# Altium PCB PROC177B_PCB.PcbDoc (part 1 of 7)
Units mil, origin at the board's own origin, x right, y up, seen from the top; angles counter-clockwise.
Board outline 4257.98 x 1561.15 mil, 4 copper layers (Top Layer, Int1 (GND), Int2 (PWR), Bottom Layer), stack 63.572 mil thick; 461 components, 307 nets, 1564 pads, 607 vias.
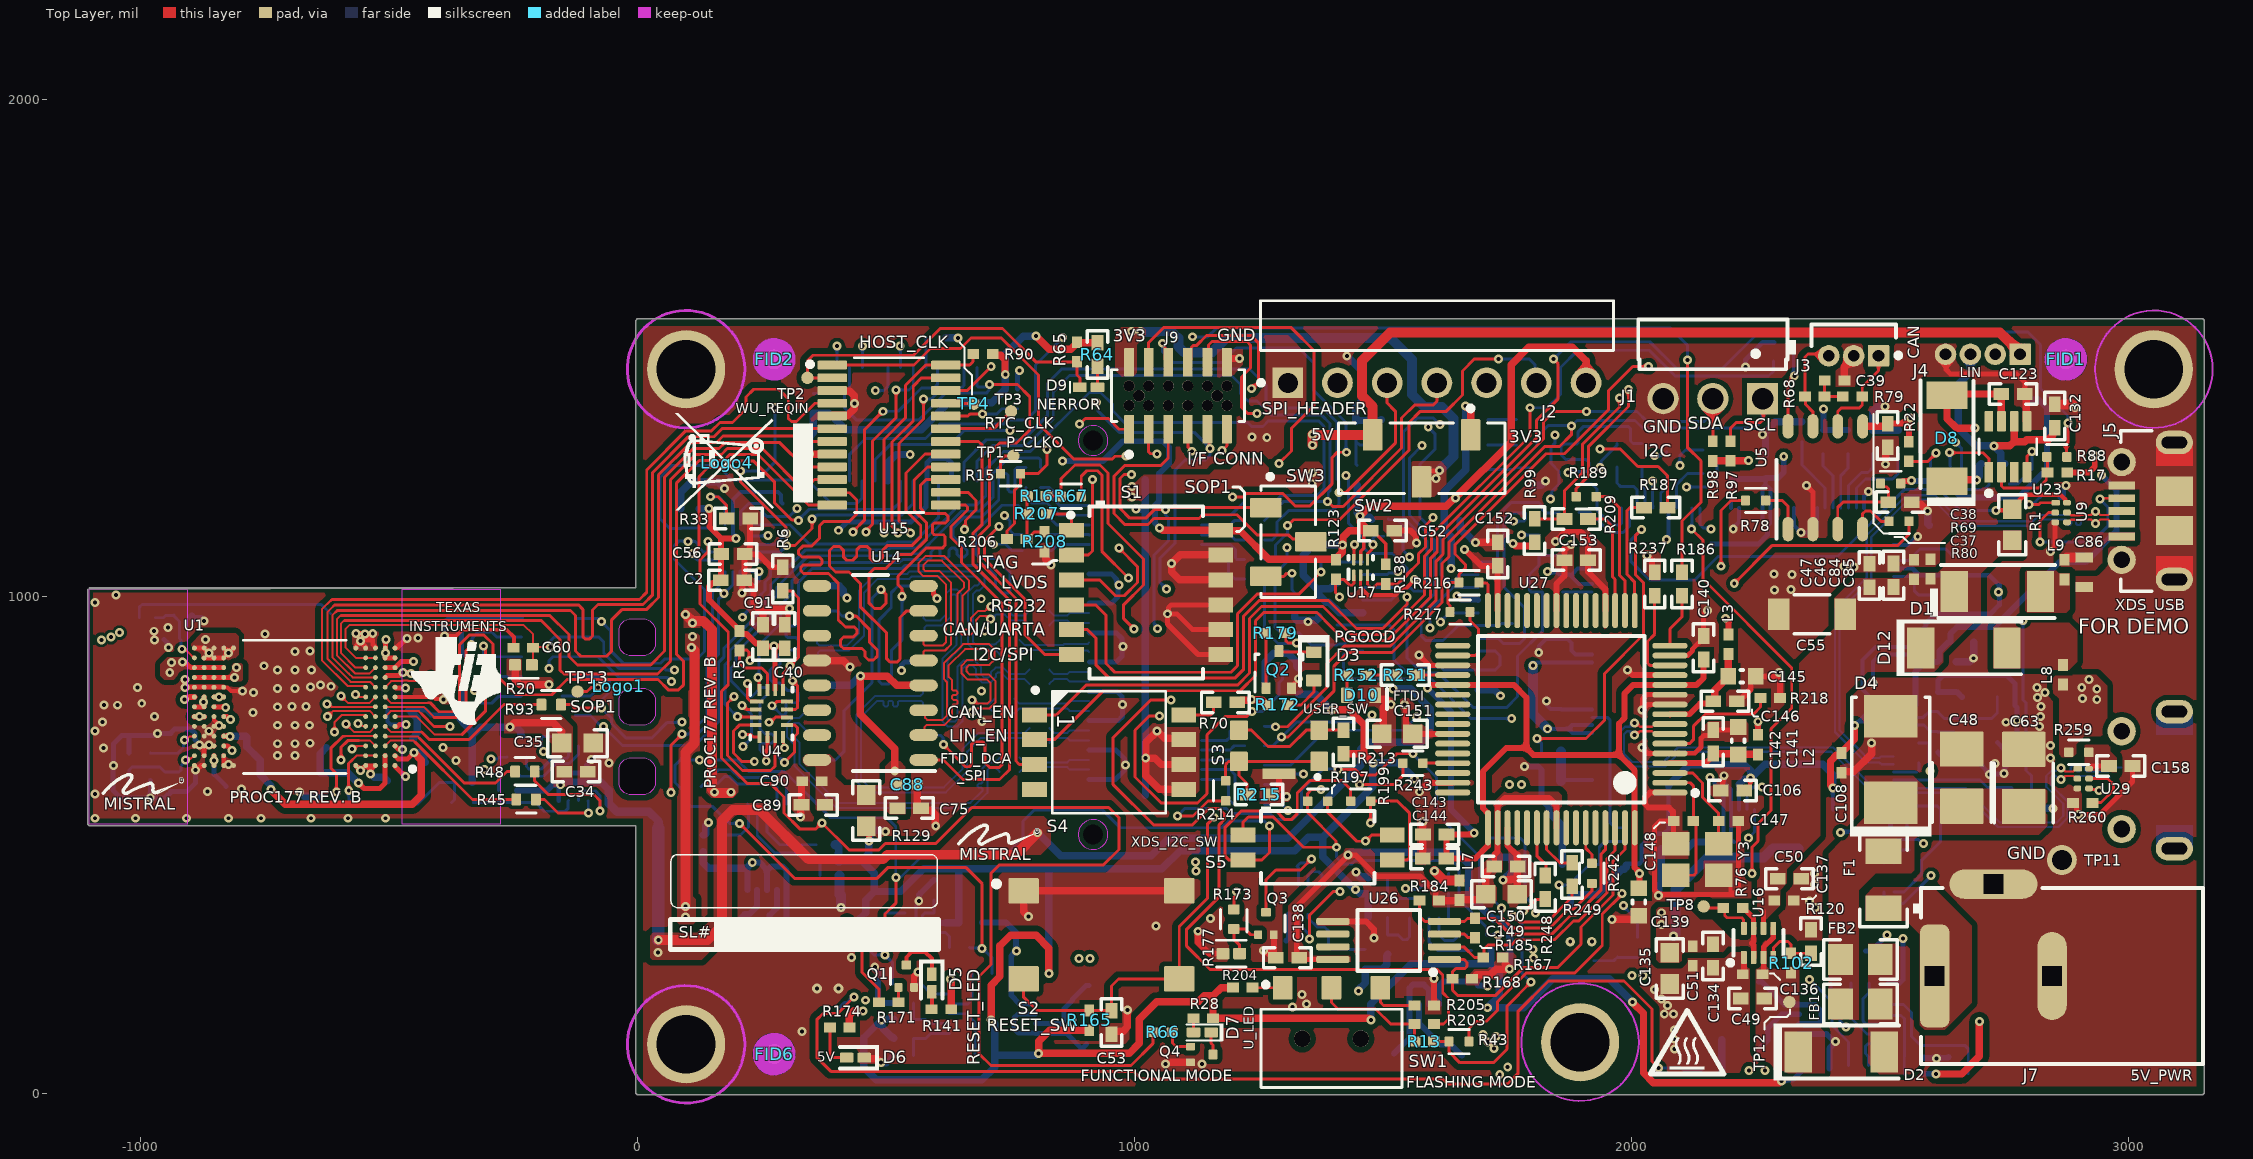
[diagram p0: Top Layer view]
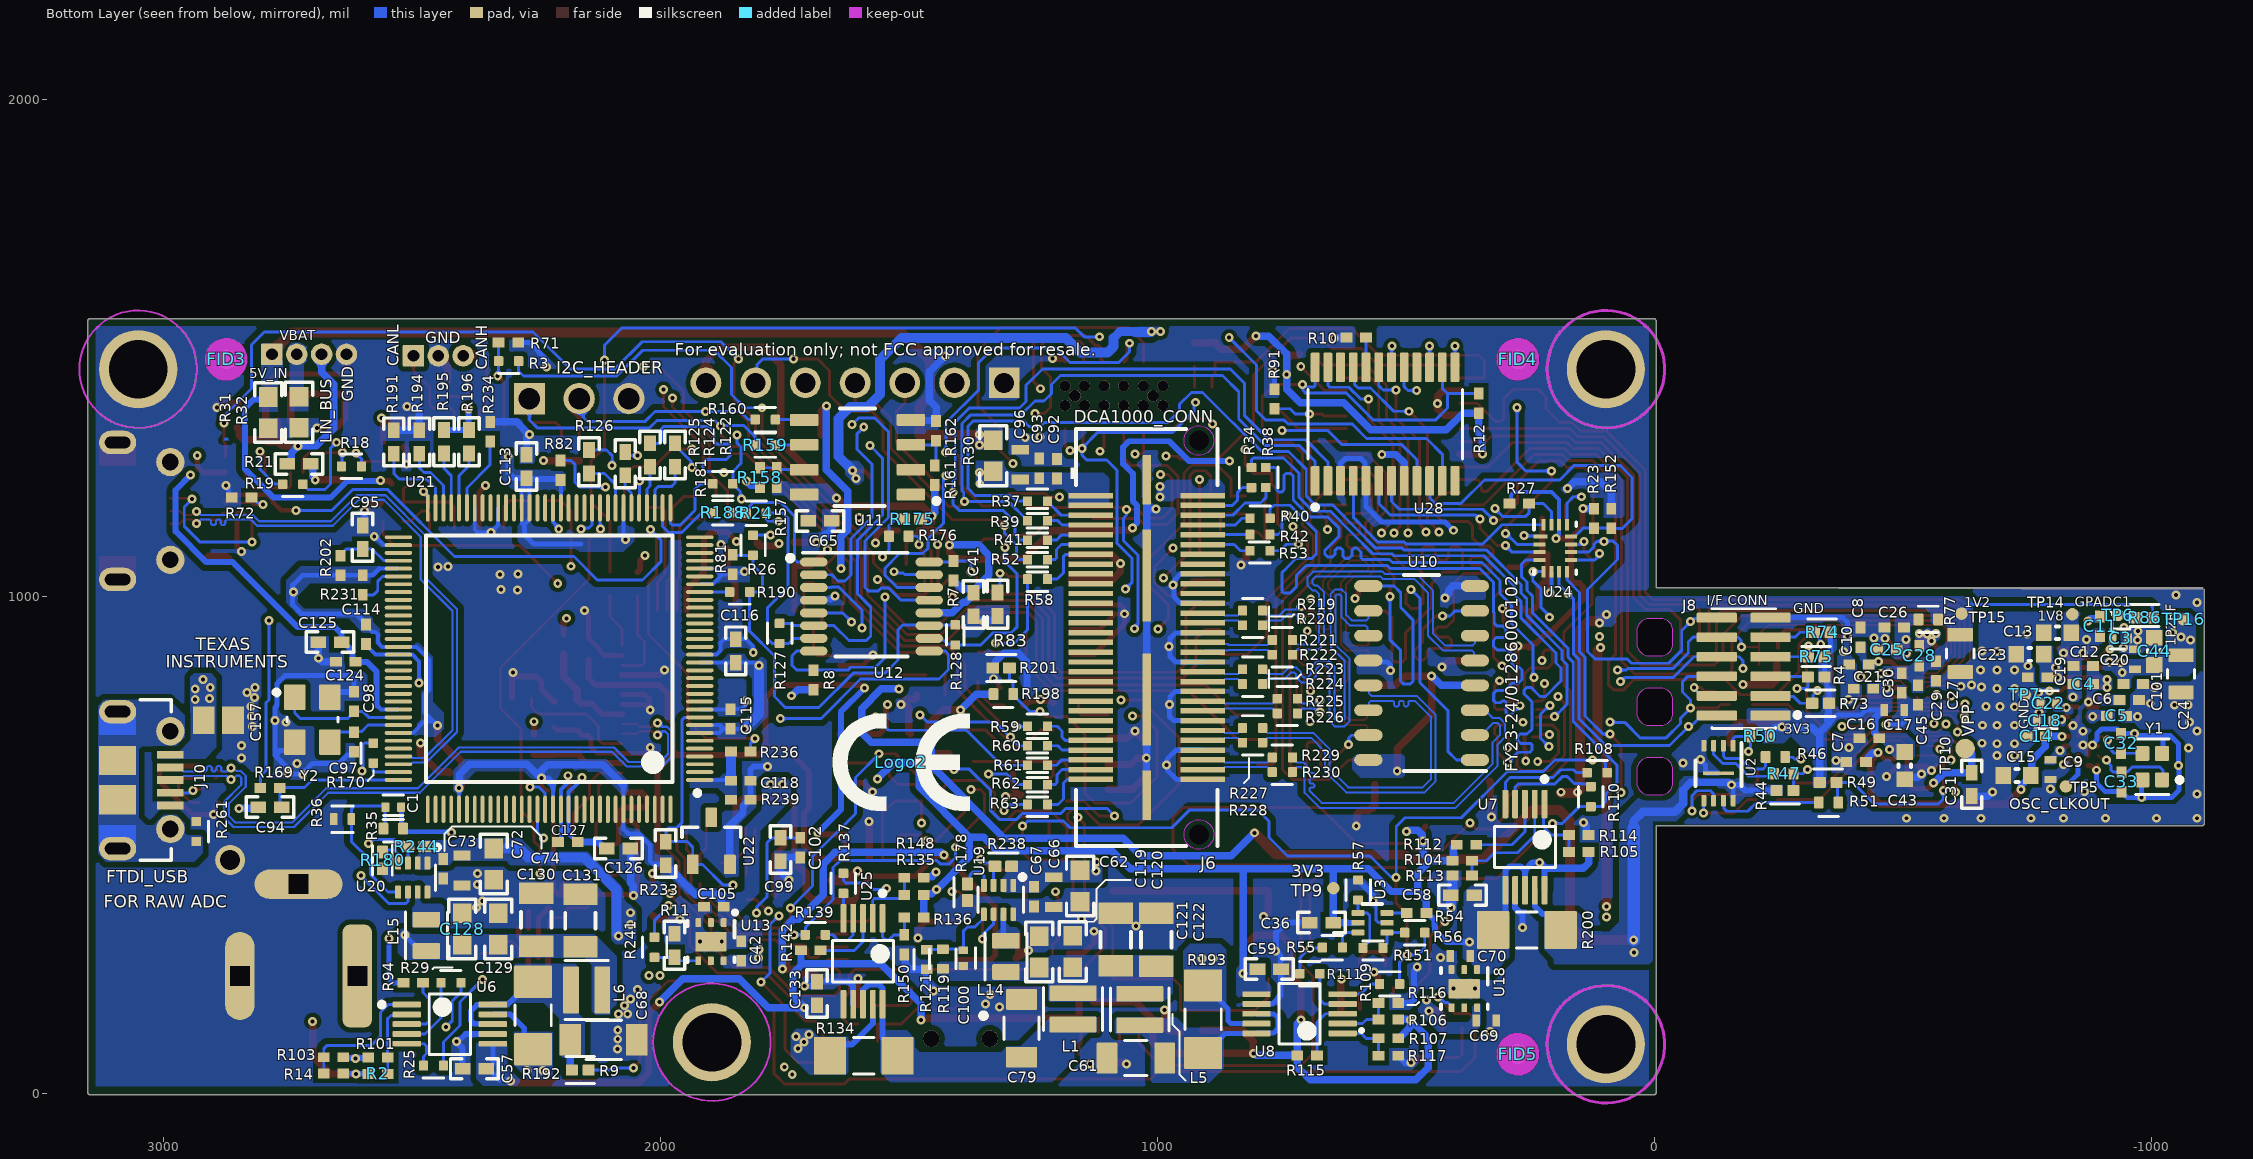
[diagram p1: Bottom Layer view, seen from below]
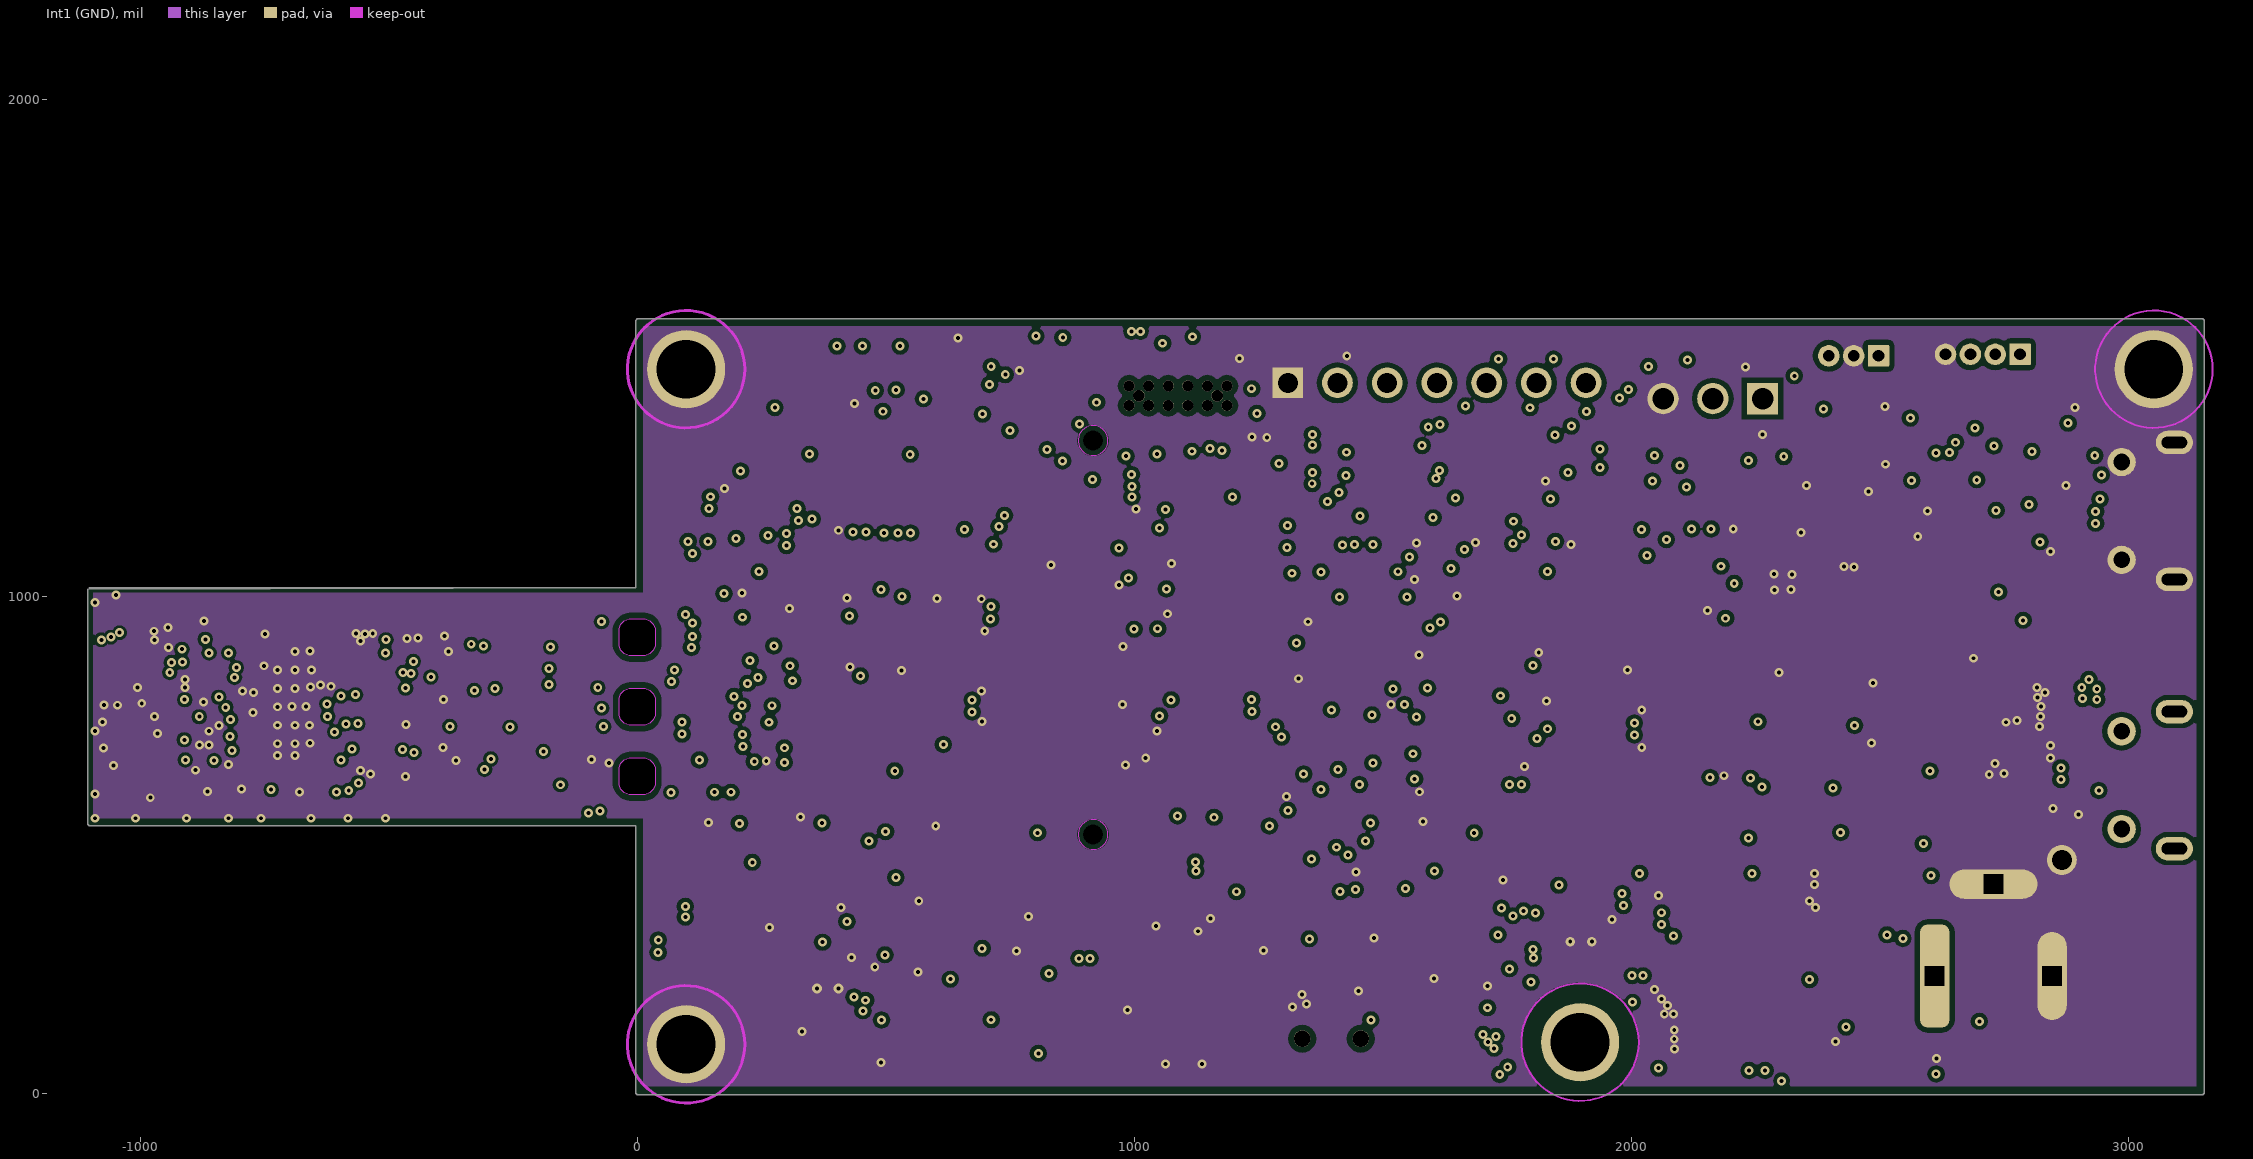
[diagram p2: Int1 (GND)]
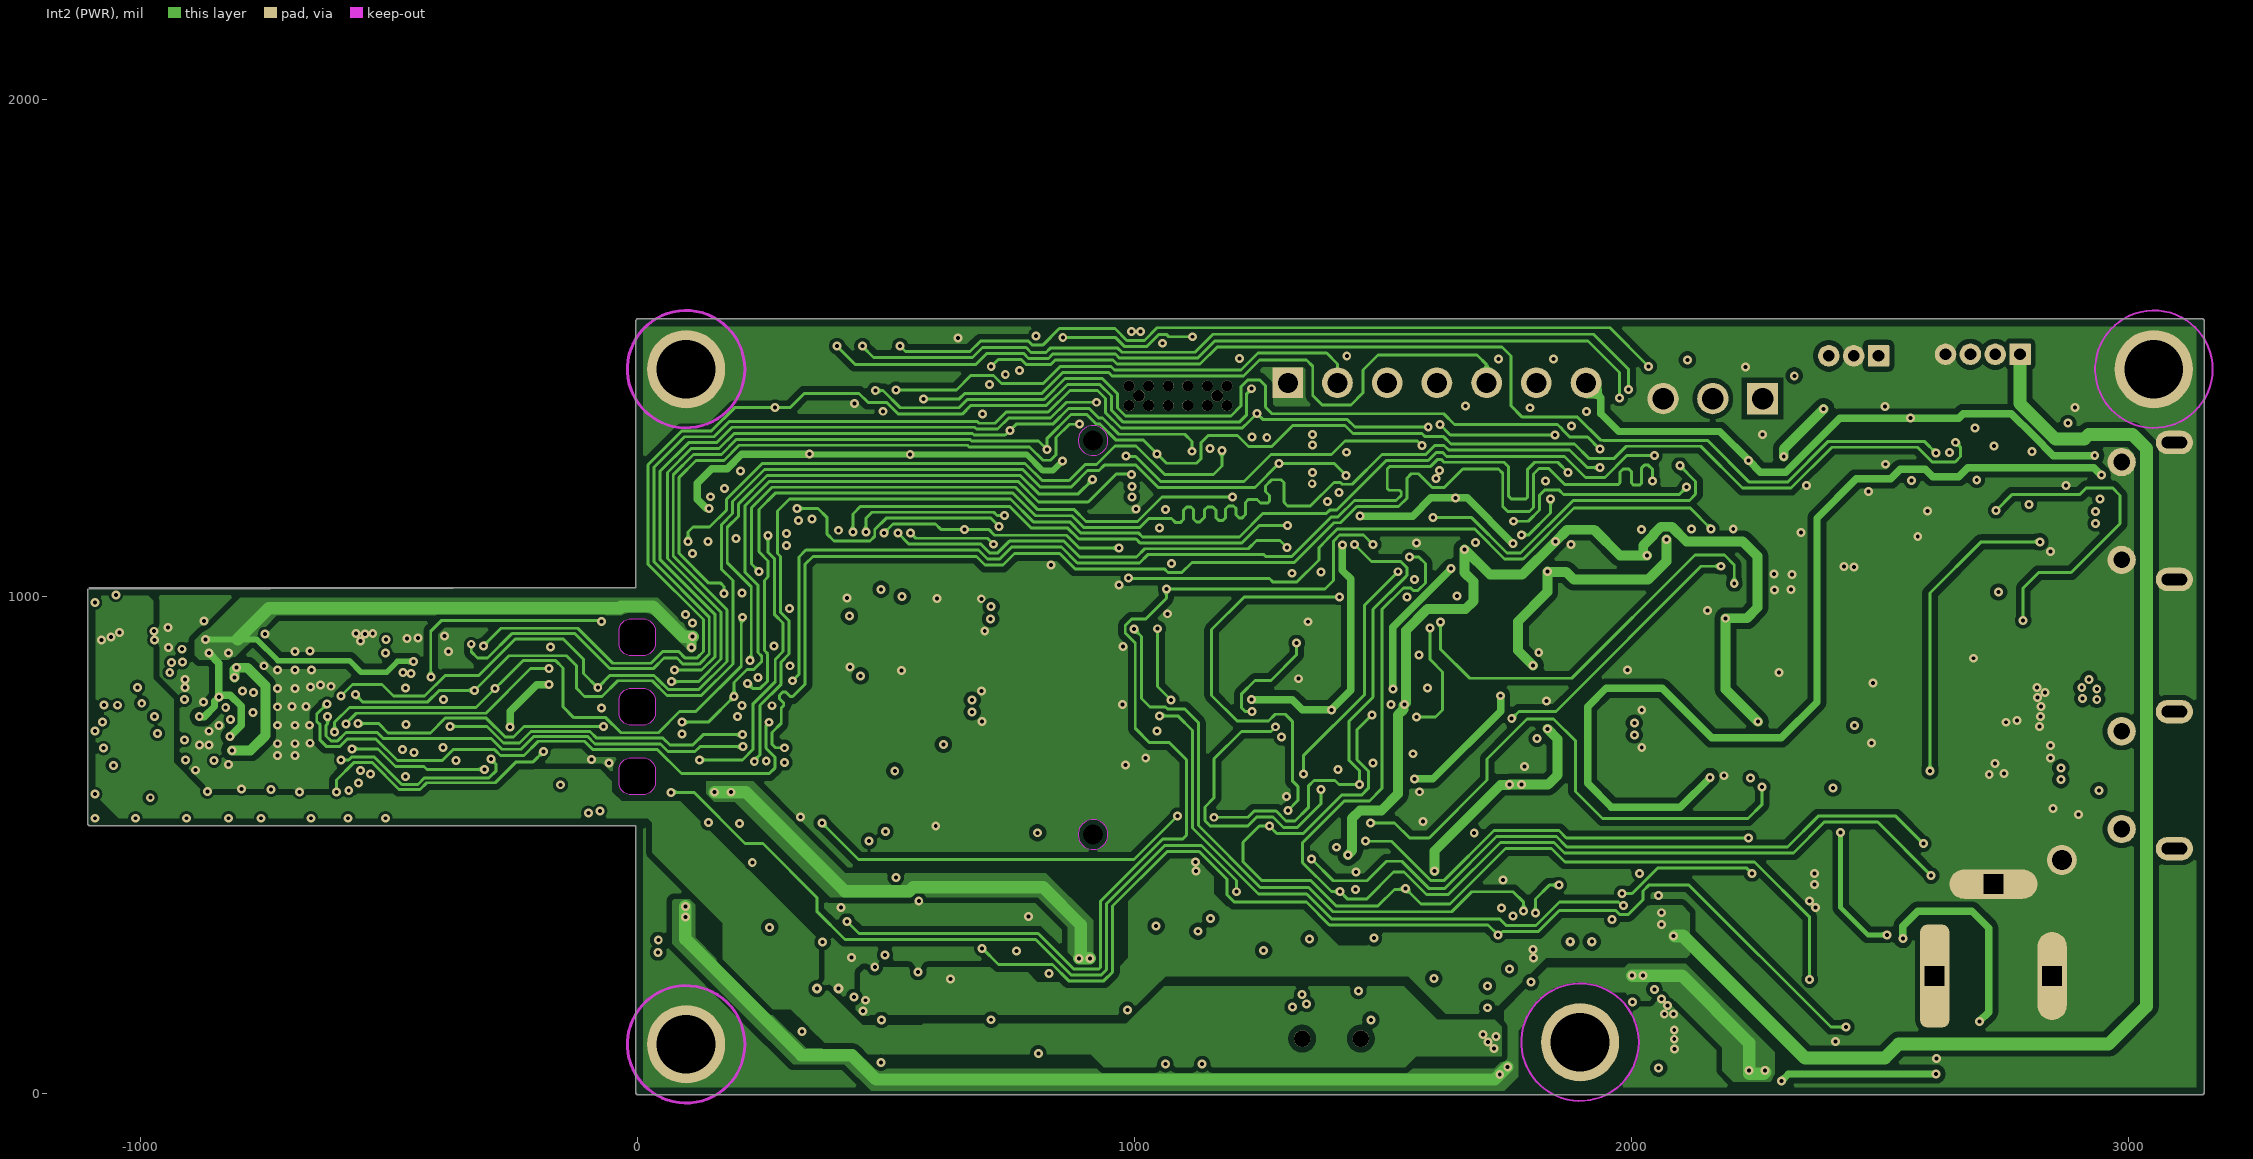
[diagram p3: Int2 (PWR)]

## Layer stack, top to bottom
Top Solder: solder mask 1, Dk 3.5
Top Layer: signal copper 1.85
Dielectric 1: prepreg 1.779, Iteq IT180A Prepreg 106 RC71-NEW, Dk 3.79
Dielectric 2: prepreg 1.779, Iteq IT180A Prepreg 106 RC71-NEW, Dk 3.79
Int1 (GND): signal copper 2.756
Dielectric 3: core 47.244, Iteq IT180A 50 mil core 1/1, Dk 4.28
Int2 (PWR): signal copper 2.756
Dielectric 4: prepreg 1.779, Iteq IT180A Prepreg 106 RC71-NEW, Dk 3.79
Dielectric 5: prepreg 1.779, Iteq IT180A Prepreg 106 RC71-NEW, Dk 3.79
Bottom Layer: signal copper 1.85
Bottom Solder: solder mask 1, Dk 3.5

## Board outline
-1082.65,538.25 -3,538.25 -3.02,0 0,-3.02 3149.61,-3.02 3152.62,0 3152.62,1555.12 3149.49,1558.13 0.14,1558.13 -3.01,1554.89 -3,1016.79 -1082.65,1016.79 -1102.34,1016.79 -3,1016.79 -1105.36,1013.78 -1105.36,541.34 -1102.34,538.24
cut-out: -11.37,600.39 -16.34,600.39 -25.53,604.2 -32.56,611.23 -36.37,620.42 -36.37,625.39 -36.37,650.05 -36.37,655.02 -32.56,664.21 -25.53,671.24 -16.34,675.05 -11.37,675.05 11.4,675.05 16.38,675.05 25.56,671.24 32.6,664.21 36.4,655.02 36.4,650.05 36.4,625.39 36.4,620.42 32.6,611.23 25.56,604.2 16.38,600.39 11.4,600.39
cut-out: -11.36,740.23 -16.34,740.23 -25.52,744.04 -32.56,751.07 -36.36,760.26 -36.36,765.23 -36.36,789.89 -36.36,794.86 -32.56,804.05 -25.52,811.08 -16.33,814.89 -11.36,814.89 11.41,814.89 16.38,814.89 25.57,811.08 32.6,804.05 36.41,794.86 36.41,789.89 36.41,765.23 36.41,760.26 32.6,751.07 25.57,744.04 16.38,740.23 11.41,740.23
cut-out: -36.36,905.07 -36.36,929.72 -36.36,934.7 -32.56,943.89 -25.53,950.92 -16.34,954.72 -11.36,954.72 11.4,954.72 16.38,954.72 25.57,950.92 32.6,943.88 36.4,934.7 36.4,929.72 36.4,905.07 36.4,900.1 32.6,890.91 25.56,883.88 16.38,880.07 11.4,880.07 -11.36,880.07 -16.34,880.07 -25.53,883.88 -32.56,890.91 -36.36,900.1 -36.36,905.07

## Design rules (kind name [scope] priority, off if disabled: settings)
AcuteAngle [All] p1 off: minimum=4.50000000000000E+0001 checktracksonly=FALSE
AssemblyTestPointUsage [All] p1: valid=2
BoardOutlineClearance GND_VIA [IsVia and InNet('GND')] p1: gap=2 ignorepadtopadclearanceinfootprint=FALSE
BoardOutlineClearance track_silk [IsTrack and (OnBottomSilkscreen or OnTopSilkscreen)] p2: gap=0 ignorepadtopadclearanceinfootprint=FALSE
BoardOutlineClearance FAB_TEXT [WithinRoom('FAB TEXT')] p3: gap=0 ignorepadtopadclearanceinfootprint=FALSE
BoardOutlineClearance txt [IsText and (OnBottomSilkscreen or OnTopSilkscreen)] p4: gap=1 ignorepadtopadclearanceinfootprint=FALSE
BoardOutlineClearance [All] p5: gap=12 ignorepadtopadclearanceinfootprint=FALSE except(0: Poly-OutlineEdge)
Clearance Clearance_Keepout [IsKeepOut] p1: gap=0 ignorepadtopadclearanceinfootprint=TRUE
Clearance BGA_SENSOR [WithinRoom('sensor')] p2: gap=6 ignorepadtopadclearanceinfootprint=TRUE except(0: Text-Hole; 4: Arc-Track Track-Track Track-SMDPad Track-Via; 5: Arc-Arc Arc-SMDPad SMDPad-Via; 5.1: Track-Region SMDPad-SMDPad; 5.6: Via-Region; 7: Arc-Fill Arc-Poly Arc-Region Track-Fill SMDPad-Region THPad-Region; 7.3: Region-Region; 8: SMDPad-Fill SMDPad-Poly THPad-Fill THPad-Poly; 10: Fill-Fill Fill-Poly Fill-Region Poly-Poly Poly-Region; 10.6: Fill-Hole Region-Hole; 11: Poly-Hole; 12: Track-Poly)
Clearance Clearance_diff_ext [InAnyDifferentialPair vs OnTopLayer or OnBottomLayer] p3: gap=6 ignorepadtopadclearanceinfootprint=TRUE except(0: Text-Hole; 4.5: Track-Track; 5: Arc-Arc Arc-Track Arc-SMDPad Track-SMDPad Track-Region; 5.1: SMDPad-SMDPad; 6.2: Region-Region; 7: Arc-Fill Arc-Region Track-Fill; 8: Arc-Poly SMDPad-Fill THPad-Fill Via-Poly Fill-Poly; 10: SMDPad-Poly THPad-Poly Fill-Fill Fill-Region Poly-Region; 11: Fill-Hole Poly-Hole Region-Hole; 12: Track-Poly Poly-Poly)
Clearance [All] p4: gap=6 ignorepadtopadclearanceinfootprint=TRUE except(0: Text-Hole; 5: Arc-Arc Arc-Track Arc-SMDPad Track-SMDPad SMDPad-Region THPad-Region; 5.1: SMDPad-SMDPad; 5.8: Track-Region; 5.9: Via-Region; 6.2: Region-Region; 7: Arc-Fill Arc-Region Track-Fill; 8: Arc-Poly SMDPad-Fill THPad-Fill Via-Poly Fill-Poly; 10: SMDPad-Poly THPad-Poly Fill-Fill Fill-Region Poly-Region; 10.9: Region-Hole; 11: Fill-Hole Poly-Hole; 12: Track-Poly Poly-Poly)
Clearance Clearance_BGA [WithinRoom('BGA1')] p5: gap=4 ignorepadtopadclearanceinfootprint=FALSE except(8: Fill-Fill Fill-Poly Fill-Region Poly-Poly Poly-Region Region-Region; 10: Fill-Hole Poly-Hole Region-Hole)
Clearance "top and bottom" [OnTopLayer or OnBottomLayer] p6: gap=6 ignorepadtopadclearanceinfootprint=TRUE except(5: Arc-Arc Arc-Track Arc-SMDPad Arc-Hole Track-SMDPad Track-Hole SMDPad-Hole THPad-Hole Via-Hole Text-Hole; 5.1: SMDPad-SMDPad; 7: Arc-Fill Arc-Poly Arc-Region Track-Fill Track-Region; 8: Track-Poly SMDPad-Fill SMDPad-Poly SMDPad-Region THPad-Fill THPad-Poly THPad-Region Via-Fill Via-Poly Via-Region Poly-Poly; 10: Fill-Fill Fill-Poly Fill-Region Poly-Region Region-Region; 11: Fill-Hole Poly-Hole Region-Hole)
Clearance Clearance_KO-J5 [IsKeepOut and IsTrack vs InComponent('J5')] p7: gap=19.6 ignorepadtopadclearanceinfootprint=FALSE except(9: SMDPad-SMDPad)
Clearance "Inner layers" [OnLayer('L3_SIGNAL 1') OR ('L6_SIGNAL 4') vs InNet('GND')] p8: gap=6 ignorepadtopadclearanceinfootprint=TRUE except(0: Text-Hole; 5: Arc-Arc Arc-Track Arc-SMDPad Track-Track Track-SMDPad; 5.1: SMDPad-SMDPad; 7: Arc-Fill Arc-Poly Arc-Region Track-Fill Track-Region; 8: SMDPad-Fill SMDPad-Poly SMDPad-Region THPad-Fill THPad-Poly THPad-Region; 10: Fill-Fill Fill-Poly Fill-Region Poly-Region Region-Region; 11: Fill-Hole Poly-Hole Region-Hole; 15: Track-Poly; 20: Poly-Poly)
Clearance Same_net [All] p9: gap=0 ignorepadtopadclearanceinfootprint=TRUE
ComponentClearance ComponentClearance_MatingCon-3D [All vs not InAnyComponent] p1: gap=0 collisioncheckmode=3 verticalgap=0 showdistances=FALSE
ComponentClearance "ComponentClearance_WEE Logo" [InComponent('Logo4')] p2: gap=0 collisioncheckmode=3 verticalgap=0 showdistances=TRUE
ComponentClearance ComponentClearance_R77 [InComponent('R77') vs InComponent('Logo1')] p3: gap=0 collisioncheckmode=3 verticalgap=0 showdistances=TRUE
ComponentClearance ComponentClearance_Logo [InComponentClass('Logo')] p4: gap=0 collisioncheckmode=3 verticalgap=0 showdistances=TRUE
ComponentClearance "ComponentClearance_Mounting Holes_Fiducial Marks" [InComponentClass('FiducialMark') vs InPadClass('Mounting Holes PADS')] p5: gap=50 collisioncheckmode=3 verticalgap=10 showdistances=TRUE
ComponentClearance [All] p6: gap=1 collisioncheckmode=3 verticalgap=10 showdistances=TRUE
DiffPairsRouting 100E [InDifferentialPairClass('100E')] p1: maxlimit=6 minlimit=6 mostfreqgap=6 toplayer_minwidth=4 toplayer_maxwidth=4 toplayer_prefwidth=4 midlayer1_minwidth=4 midlayer1_maxwidth=4 midlayer1_prefwidth=4 midlayer2_minwidth=4 midlayer2_maxwidth=4 midlayer2_prefwidth=4 bottomlayer_minwidth=4 bottomlayer_maxwidth=4 bottomlayer_prefwidth=4 maxuncoupledlength=500
DiffPairsRouting 90E [InDifferentialPairClass('90E')] p2: maxlimit=4.5 minlimit=4.5 mostfreqgap=4.5 toplayer_minwidth=4.5 toplayer_maxwidth=4.5 toplayer_prefwidth=4.5 midlayer1_minwidth=4.5 midlayer1_maxwidth=4.5 midlayer1_prefwidth=4.5 midlayer2_minwidth=4.5 midlayer2_maxwidth=4.5 midlayer2_prefwidth=4.5 bottomlayer_minwidth=4.5 bottomlayer_maxwidth=4.5 bottomlayer_prefwidth=4.5 maxuncoupledlength=500
FabricationTestPointUsage TestPointUsage [All] p1: valid=2 allowmultiple=FALSE
FabricationTestpoint Testpoint [All] p1: side=3 testpointundercomponent=TRUE minsize=40 maxsize=100 preferedsize=60 minholesize=0 maxholesize=40 preferedholesize=32 testpointgrid=1 allowsidetop=TRUE allowsidebottom=TRUE usegrid=TRUE gridtolerance=0.01
FanoutControl Fanout_LCC [IsLCC] p1: bgadir=Out bgaviamode=Centered fanoutstyle=Auto fanoutdirection=Alternating viagrid=1 // Fanout_LCC (Default Rule)
FanoutControl Fanout_BGA [IsBGA] p2: bgadir=Out bgaviamode=Centered fanoutstyle=Auto fanoutdirection=Alternating viagrid=1 // Fanout_BGA (Default Rule)
FanoutControl Fanout_Default [All] p4: bgadir=Out bgaviamode=Centered fanoutstyle=Auto fanoutdirection=Alternating viagrid=1 // Fanout_Default (Default Rule)
FanoutControl Fanout_Small [(CompPinCount < 5)] p5: bgadir=Out bgaviamode=Centered fanoutstyle=Auto fanoutdirection=OutThenIn viagrid=1 // Fanout_Small (Default Rule)
Height Room_Hieght [WithinRoom('Room_Hieght 1 MM')] p1: minheight=0 maxheight=41.34 prefheight=39.37
HoleSize [All] p1: absolutevalues=TRUE maxlimit=280 minlimit=5.9 maxpercent=80.000 minpercent=20.000
HoleToHoleClearance HoleToHoleClearance_1 [WithinRoom('BGA1')] p1: gap=4 allowstackedmicrovias=FALSE
MatchedLengths DiffPair_MatchedLengths [InDifferentialPairClass('100E')] p1: tolerance=1000 checknetsindiffpair=FALSE checkdiffpairvsdiffpair=TRUE checkxsignals=TRUE checkothers=TRUE
MatchedLengths MatchedLengths_LVDS_D [InNetClass('LVDS_D')] p2: tolerance=5 checknetsindiffpair=FALSE checkdiffpairvsdiffpair=TRUE checkxsignals=TRUE checkothers=TRUE
MatchedLengths MatchedLengths_XDS_DCA_T [InxSignalClass('XDS_DCA_T')] p3: tolerance=5 checknetsindiffpair=FALSE checkdiffpairvsdiffpair=TRUE checkxsignals=TRUE checkothers=TRUE
MatchedLengths MatchedLengths_XDSET [InxSignalClass('XDSET')] p4: tolerance=2.5 checknetsindiffpair=FALSE checkdiffpairvsdiffpair=TRUE checkxsignals=TRUE checkothers=TRUE
MatchedLengths MatchedLengths_DCA_T [InxSignalClass('DCA_T')] p5: tolerance=1000 checknetsindiffpair=FALSE checkdiffpairvsdiffpair=TRUE checkxsignals=TRUE checkothers=TRUE
MatchedLengths MatchedLengths_XDS_T [InxSignalClass('XDS_T')] p6: tolerance=50 checknetsindiffpair=FALSE checkdiffpairvsdiffpair=TRUE checkxsignals=TRUE checkothers=TRUE
MatchedLengths MatchedLengths_QSPI [InxSignalClass('QSPI')] p7: tolerance=200 checknetsindiffpair=FALSE checkdiffpairvsdiffpair=TRUE checkxsignals=TRUE checkothers=TRUE
MatchedLengths MatchedLengths_CAN [InxSignalClass('CAN')] p8: tolerance=2.5 checknetsindiffpair=FALSE checkdiffpairvsdiffpair=TRUE checkxsignals=TRUE checkothers=TRUE
MatchedLengths MatchedLengths_RADAR_LVDS_DATA [InNetClass('RADAR_LVDS_DATA')] p9: tolerance=5 checknetsindiffpair=FALSE checkdiffpairvsdiffpair=TRUE checkxsignals=TRUE checkothers=TRUE
MatchedLengths MatchedLengths_RADAR_LVDS [InxSignalClass('RADAR_LVDS')] p10: tolerance=2.5 checknetsindiffpair=FALSE checkdiffpairvsdiffpair=TRUE checkxsignals=TRUE checkothers=TRUE
MinimumAnnularRing MinimumAnnularRing_ThermalPadVias [IsVia and InAnyComponent] p1: minimumring=3.9
MinimumAnnularRing [All] p2: minimumring=3.9
MinimumSolderMaskSliver MinimumSolderMaskSliver_Logo [InComponentClass('Logo') vs InComponentClass('Logo')] p1: minsoldermaskwidth=0.7
MinimumSolderMaskSliver [All] p2: minsoldermaskwidth=3.5
PlaneConnect [All] p1: planeconnectstyle=Relief reliefexpansion=10 reliefentries=4 reliefconductorwidth=10 reliefairgap=10
PolygonConnect [All] p1: connectstyle=Direct reliefconductorwidth=10 reliefentries=4 polygonreliefangle="90 Angle" airgapwidth=10
RoomDefinition "FAB TEXT" [False vs False] p1: confinementstyle=ConfineIn formatcopy=TRUE lockcomponents=FALSE outline -336,-791.4 546,-791.4 546,-964.4 -336,-964.4
RoomDefinition sensor [False vs False] p2: confinementstyle=ConfineIn formatcopy=TRUE lockcomponents=FALSE outline -1102.34,1013.78 80,1013.78 80,541.26 -1102.34,541.26
RoutingVias ThermalPadVias [IsVia and InAnyComponent] p1: holewidth=7.87 width=19.68 viastyle="Through Hole" minholewidth=5 minwidth=13 maxholewidth=12.99 maxwidth=23.62
RoutingVias [All] p2: holewidth=12.2 width=22.4 viastyle="Through Hole" minholewidth=5.9 minwidth=14 maxholewidth=20 maxwidth=40
SilkToBoardRegionClearance [Not ((IsComment or IsDesignator) And (Hide <> 'False')) and not InRegion(1000,500,4000,800)] p1:
SilkToSilkClearance [All] p1: silktosilkclearance=3
SilkToSolderMaskClearance SilkToSolderMaskClearance_OutLine [istrack and InAnyComponent] p1: minsilkscreentomaskgap=0 clearancetoexposedcopper=FALSE
SilkToSolderMaskClearance SilkscreenOverComponentPads [IsPad] p2: minsilkscreentomaskgap=3 clearancetoexposedcopper=FALSE
SolderMaskExpansion [All] p1: expansion=0 istentingtop=FALSE
UnRoutedNet [All] p1: checkbadconnections=TRUE
Width [All] p1: maxlimit=40 minlimit=4 preferedwidth=5.9 midlayer1_minwidth=5.9 midlayer2_minwidth=5.9 bottomlayer_minwidth=5.9 minimp=50.000000 maximp=50.000000 favimp=50.000000
12 further rules are at their usual default settings.

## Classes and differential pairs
differential pair class 100E: LVDS_0 LVDS_0_DP3 LVDS_1 LVDS_1_DP4 LVDS_2 LVDS_2_DP5 LVDS_3 LVDS_3_DP6 LVDS_CLK LVDS_CLK_DP7 LVDS_FRCLK LVDS_FRCLK_DP8
differential pair class 90E: FTDI_USB USB_DP1
component class PROC177B_Analog_MUX_SPI: C56 R10 R12 U28
component class PROC177B_I2C_SPI_Connector: J1 J2 J9 mx R83 SW2 SW3
component class PROC177B_FTDI: C138 C139 C140 C141 C142 C143 C144 C145 C146 C147 C148 C149 C150 C151 C152 C153 C157 C158 D10 J10 L2 L3 L7 m mx R99 R167 R168 R184 R185 R186 R187 R189 R209 R216 R217 R218 R237 R242 R243 R248 R249 R251 R252 R259 R260 R261 U26 U27 U29 Y3
net class RADAR_LVDS_DATA: RADAR_LVDS_CLK RADAR_LVDS_DATA0 RADAR_LVDS_DATA1 RADAR_LVDS_DATA2 RADAR_LVDS_DATA3 RADAR_LVDS_FRCLK
net class LVDS_D: LVDS_CLK_RTC_CLKIN_TP LVDS_D0_LIN_PHY_RX LVDS_D1_XDS_UARTA_RX_CAN_RX LVDS_D2_XDS_UARTA_TX_CAN_TX LVDS_D3_nERROR_LED_WD_TP LVDS_FRCLK_HOST_CLK_TP
net class POWER: 3V3_LDO_EN 5V_IN 5V_IN_USB 5V_REG CONN_5V PMIC_CLKOUT PMIC_CLKOUT_LIN_PHY_TX_SOP1 REG_1V2 REG_1V8 REG_OUT_1V2 REG_OUT_1V8 REG_PG REG_RF_1V2 SW_PR1
component class PROC177B_XDS110_Interface: C42 C94 C95 C97 C98 C99 C102 C105 C106 C108 C113 C114 C115 C116 C118 C124 C125 C126 C127 R11 R24 R26 R81 R82 R122 R124 R125 R126 R169 R170 R181 R188 R190 R191 R194 R195 R196 R197 R199 R202 R231 R233 R234 R236 R239 R241 S5 U13 U21 U22 Y2
component class PROC177B_DC_Regulators: C1 C61 C62 C66 C67 C68 C69 C70 C72 C73 C74 C79 C100 C119 C120 C121 C122 C128 C129 C130 C131 L1 L5 L6 L14 L15 Q3 R9 R35 R36 R119 R121 R173 R175 R176 R177 R178 R180 R198 R201 R238 R244 TP9 TP11 U18 U19 U20
net class Regions: 5V_IN 5V_IN_USB GND NetD1_2 NetD2_2 XTALP
component class Logo: Logo1
component class FiducialMark: FID1 FID2 FID3 FID4 FID5 FID6
component class PROC177B_Decoupling_caps_QSPI_Flash_: C4 C5 C6 C7 C8 C9 C10 C11 C12 C13 C14 C15 C16 C17 C18 C19 C20 C21 C22 C23 C24 C25 C26 C27 C28 C29 C30 C34 C35 C44 C45 C101 R44 R45 R46 R47 R48 R49 R50 R51 U2
component class PROC177B_EVM_Hardware: FID1 FID2 FID3 FID4 FID5 FID6 Logo1 Logo2 LOGO3 Logo4 ZZ1 ZZ2 ZZ3 ZZ4 ZZ5
component class Header: J1
component class PROC177B_xWRL6432AoP_Chip: C3 C31 C32 C33 C43 C60 J8 ms R4 R20 R73 R74 R75 R77 R86 R93 TP5 TP6 TP7 TP10 TP13 TP14 TP15 TP16 U1 Y1
component class PROC177B_CAN_LIN_PHY_Interface: C37 C38 C39 C123 C132 D8 J3 J4 R3 R17 R18 R19 R21 R22 R31 R32 R68 R69 R71 R78 R79 R80 R88 U5 U23
component class PROC177B_LVDS_Driver: C75 C88 C89 C90 C91 R90 R91 R129 TP2 TP3 TP4 U10 U14 U15
component class PROC177B_Temp_Current_sensors_EPROM: C36 C57 C58 C59 C65 C133 R2 R14 R25 R29 R54 R55 R56 R57 R94 R97 R98 R101 R103 R104 R105 R106 R107 R108 R109 R110 R111 R112 R113 R114 R115 R116 R117 R134 R135 R136 R137 R139 R142 R148 R150 R151 R157 R158 R159 R160 R161 R162 R192 R193 R200 U3 U6 U7 U8 U11 U25
component class AssemblyNote: ZZ1 ZZ2 ZZ3 ZZ4 ZZ5
component class PROC177B_USB_PWR_DC_Jack_Switch: C46 C47 C48 C49 C50 C51 C55 C63 C84 C85 C86 C134 C135 C136 C137 D1 D2 D3 D4 D6 D12 F1 FB1 FB2 FL1 FL2 J5 J7 L8 L9 LD1 Q2 R1 R72 R76 R102 R120 R172 R174 R179 TP8 TP12 U9 U16
component class PROC177B_DCA1000_Connector_Reset: C52 C53 C92 C93 C96 D5 D7 D9 J6 LD2 LD4 mx Q1 Q4 R28 R30 R34 R37 R38 R39 R40 R41 R42 R52 R53 R58 R59 R60 R61 R62 R63 R64 R65 R66 R123 R138 R141 R165 R171 R213 R214 R215 R219 R220 R221 R222 R223 R224 R225 R226 R227 R228 R229 R230 S2 S3 U17
component class PROC177B_Analog_Mux_SOP_Ctrl: C2 C40 C41 R5 R6 R7 R8 R13 R15 R16 R23 R27 R33 R43 R67 R70 R127 R128 R152 R203 R204 R205 R206 R207 R208 S1 S4 SW1 TP1 U4 U12 U24
differential pair FTDI_USB: +FTDI_USBD_P -FTDI_USBD_N
differential pair CAN: +CANL -CANH
differential pair LVDS_FRCLK: +NetJ6_26 -NetJ6_28
differential pair LVDS_FRCLK_DP8: +RADAR_LVDS_FRCLKP -RADAR_LVDS_FRCLKM
differential pair LVDS_CLK: +NetJ6_46 -NetJ6_44
differential pair LVDS_CLK_DP7: +RADAR_LVDS_CLKP -RADAR_LVDS_CLKM
differential pair LVDS_3: +NetJ6_32 -NetJ6_34
differential pair LVDS_3_DP6: +RADAR_LVDS_3P -RADAR_LVDS_3M
differential pair LVDS_2: +NetJ6_38 -NetJ6_40
differential pair LVDS_2_DP5: +RADAR_LVDS_2P -RADAR_LVDS_2M
differential pair LVDS_1: +NetJ6_50 -NetJ6_52
differential pair LVDS_1_DP4: +RADAR_LVDS_1P -RADAR_LVDS_1M
differential pair LVDS_0: +NetJ6_56 -NetJ6_58
differential pair LVDS_0_DP3: +RADAR_LVDS_0P -RADAR_LVDS_0M
differential pair USB_DP1: +XDSET_1_DP -XDSET_1_DM

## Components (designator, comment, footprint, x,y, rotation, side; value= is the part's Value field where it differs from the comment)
C1 "GJM1555C1H100FB01D" FP-GJM1555C1H100FB01D_0402-MFG 2538,575.6 r0 bottom value=10pF
C2 "C0402C104K8RACTU" 0402 191.79,1032 r0 top value=0.1uF
C3 "GRM155C80J105KA12D" FP-GRM155C80J105KA12D_0402-MFG -936.51,915.11 r0 bottom value=1µF
C4 "CL05B224KO5NNNC" 0402L -861.69,823.27 r0 bottom value=0.22uF
C5 "CL05B224KO5NNNC" 0402L -928.89,759.16 r0 bottom value=0.22uF
C6 "C1005X7R1H473K050BB" 0402L -954.29,791.28 r180 bottom value=0.047uF
C7 "CL05B224KO5NNNC" 0402L -404.95,666.31 r180 bottom value=0.22uF
C8 "CL05B224KO5NNNC" 0402L -413.7,917.2 r270 bottom value=0.22uF
C9 "GRM155C81C225KE11D" 0402S -796.05,651.26 r90 bottom value=2.2uF
C10 "CL05B224KO5NNNC" 0402L -410.75,862.73 r180 bottom value=0.22uF
C11 "CL05B224KO5NNNC" 0402L -895.64,939.59 r270 bottom value=0.22uF
C12 "CL05B224KO5NNNC" 0402L -861.75,859.54 r0 bottom value=0.22uF
C13 "GRM188C81A106MA73D" 0603L -809.83,926.37 r0 bottom value=10uF
C14 "CL05B224KO5NNNC" 0402L -767.2,718.18 r180 bottom value=0.22uF
C15 "GRM188C81A106MA73D" 0603L -728.49,639.33 r0 bottom value=10uF
C16 "CL05B224KO5NNNC" 0402L -431.54,714.38 r180 bottom value=0.22uF
C17 "GRM155C81C225KE11D" 0402S -481.85,770.72 r0 bottom value=2.2uF
C18 "GRM155C80J105KA12D" FP-GRM155C80J105KA12D_0402-MFG -783.92,748.92 r180 bottom value=1µF
C19 "CL05B224KO5NNNC" 0402L -769.73,837.09 r180 bottom value=0.22uF
C20 "GRM155C81C225KE11D" 0402S -965.93,873.42 r270 bottom value=2.2uF
C21 "CL05B224KO5NNNC" 0402L -419.92,813.77 r180 bottom value=0.22uF
C22 "GRM155C80J105KA12D" FP-GRM155C80J105KA12D_0402-MFG -791.25,784.21 r180 bottom value=1µF
C23 "GRM188C81A106MA73D" 0603L -754.48,882.83 r0 bottom value=10uF
C24 "GRM21BR71C475KE51L" FP-GRM21BR71C475KE51L_0805-MFG -1058.5,843.8 r90 bottom value=4.7µF
C25 "CL05B224KO5NNNC" 0402L -466.71,892.5 r180 bottom value=0.22uF
C26 "CL05B224KO5NNNC" 0402L -481.51,937 r180 bottom value=0.22uF
C27 "GRM21BR71C475KE51L" FP-GRM21BR71C475KE51L_0805-MFG -614.09,884.93 r90 bottom value=4.7µF
C28 "CL05B224KO5NNNC" 0402L -531.9,880.26 r270 bottom value=0.22uF
C29 "CL05B224KO5NNNC" 0402L -565.75,849.51 r90 bottom value=0.22uF
C30 "C0402C103K4RACTU" 0402L -496.85,825.26 r270 bottom value=0.01uF
C31 "C1005X7R1H104K050BE" 0402 -637.54,621.5 r270 bottom value=0.1uF
C32 "GJM1555C1H4R7BB01D" 0402L -937.91,703.76 r270 bottom value=4.7pF
C33 "GJM1555C1H4R7BB01D" 0402L -938.64,626.35 r90 bottom value=4.7pF
C34 "C1005X7R1H104K050BE" 0402 -123.28,647.05 r0 top value=0.1uF
C35 "CL10B105KO8NFNC" 0603 -119.98,704.58 r180 top value=1uF
C36 "GCM155R71H104KE02D" 0402 670.48,343.24 r0 bottom value=0.1uF
C37 "C0402C104K8RACTU" 0402 2540.57,1189.11 r180 top value=0.1uF
C38 "C0402C104K8RACTU" 0402 2515.6,1323.38 r90 top value=0.1uF
C39 "GCM155R71H472KA37D" 0402L 2409,1433.6 r180 top value=4700pF
C40 "C0402C104K8RACTU" 0402 296.84,918.94 r90 top value=0.1uF
C41 "C0402C104K8RACTU" 0402 1370.83,983.24 r270 bottom value=0.1uF
C42 "C1005X7S1A225K050BC" 0402_065L 1837.69,286.05 r90 bottom value=2.2uF
C43 "GRM188C81A106MA73D" 0603L -502.75,659.1 r270 bottom value=10uF
C44 "GRM188C81A106MA73D" 0603L -1004.41,889.04 r90 bottom value=10uF
C45 "C0402C103K4RACTU" 0402L -529.26,801.31 r270 bottom value=0.01uF
C46 "GRM155R61A106ME11D" 0402 2527.55,1042.09 r270 top value=10uF
C47 "GRM155R61A106ME11D" 0402 2479.01,1041.64 r90 top value=10uF
C48 "T491B476K010AT" 3528-21 2664.63,634.94 r90 top value=47uF
C49 "GCM155R71H104KE02D" 0402 2243.72,190.48 r180 top value=0.1uF
C50 "GCM155R71H104KE02D" 0402 2317.97,431.63 r180 top value=0.1uF
C51 "GRT155C81A105KE01D" 0402L 2123.57,276.24 r270 top value=1uF
C52 "GCM155R71H104KE02D" 0402 1499.21,1131.87 r180 top value=0.1uF
C53 "GCM155R71H104KE02D" 0402 954,142.6 r270 top value=0.1uF
C55 "GRM31CR61A476KE15L" 1206_180 2363.38,963.49 r180 top value=47uF
C56 "GCM155R71H104KE02D" 0402 192.53,1084.61 r0 top value=0.1uF
C57 "GCM155R71H104KE02D" 0402 2374.77,49.43 r0 bottom value=0.1uF
C58 "GCM155R71H104KE02D" 0402 386.7,398.47 r0 bottom value=0.1uF
C59 "GCM155R71H104KE02D" 0402 775.79,249.69 r180 bottom value=0.1uF
C60 "CL05B224KO5NNNC" 0402L -228.99,896.44 r0 top value=0.22uF
C61 "GRM31CR70J226ME19K" FP-GRM31CR70J226ME19K_1206-MFG 1044.03,70.8 r180 bottom value=22µF
C62 "GRM188C81A106MA73D" 0603 1156.35,416.75 r270 bottom value=10uF
C63 "T491B476K010AT" 3528-21 2789.33,634.39 r90 top value=47uF
C65 "GCM155R71H104KE02D" 0402 1679.36,1151.54 r180 bottom value=0.1uF
C66 "GRM188R71C474KA88D" 0603S 1208.99,404.57 r270 bottom value=0.47uF
C67 "GRM1555C1H471JA01D" 0402L 1248.84,395.61 r270 bottom value=470pF
C68 "GRM31CR60J476ME19L" 1206_180 2114.72,107.45 r0 bottom value=47uF
C69 "GRM155C81C225KE11D" 0402S 339.16,146.27 r0 bottom value=2.2uF
C70 "GRM155C81C225KE11D" 0402S 391.76,276.58 r180 bottom value=2.2uF
C72 "GRM188C81A106MA73D" 0603 2335.86,460.98 r270 bottom value=10uF
C73 "GRM188R71C474KA88D" 0603S 2399.71,448.21 r270 bottom value=0.47uF
C74 "GRM1555C1H471JA01D" 0402L 2437.19,451.83 r270 bottom value=470pF
C75 "GCM155R71H104KE02D" 0402 547.26,573.55 r0 top value=0.1uF
C79 "GRM31CR70J226ME19K" FP-GRM31CR70J226ME19K_1206-MFG 1274,130.6 r270 bottom value=22µF
C84 "GCM155C71A474KE36D" 0402L 2568.88,1053.8 r90 top value=0.47uF
C85 "GCM155R71C224KE02D" 0402L 2601.76,1054.73 r270 top value=0.22uF
C86 "GRT188R61A106KE13D" 0603S 2910.89,1048.17 r90 top value=10uF
C88 "GCM155R71E103KA37D" 0402L 543.72,620.74 r0 top value=0.01uF
C89 "GCM155R71H104KE02D" 0402 354.19,580.27 r180 top value=0.1uF
C90 "GCM155R71E103KA37D" 0402L 351.56,627.8 r180 top value=0.01uF
C91 "GCM155R71H104KE02D" 0402 253.09,918.94 r90 top value=0.1uF
C92 "GCM155C71A474KE36D" 0402L 1202.77,1256.36 r90 bottom value=0.47uF
C93 "GRT155C81A105KE01D" 0402L 1238.41,1257.18 r90 bottom value=1uF
C94 "C0402C104K8RACTU" 0402 2786,575.6 r0 bottom value=0.1uF
C95 "C0402C104K8RACTU" 0402 2599.45,1118.65 r270 bottom value=0.1uF
C96 "GRT188R61A106KE13D" 0603S 1276.77,1264.52 r270 bottom value=10uF
C97 "CC0402DRNPO9BN8R0" 0402L 2616.98,706.75 r90 bottom value=8pF
C98 "CC0402DRNPO9BN8R0" 0402L 2616.98,787.95 r270 bottom value=8pF
C99 "C0402C104K8RACTU" 0402 1759.12,490.29 r90 bottom value=0.1uF
C100 "GJM1555C1H100FB01D" FP-GJM1555C1H100FB01D_0402-MFG 1391.2,272.06 r90 bottom value=10pF
C101 "CL05B224KO5NNNC" 0402L -962.32,823.13 r0 bottom value=0.22uF
C102 "GCM155R71E103KA37D" 0402L 1719.12,494.23 r90 bottom value=0.01uF
C105 "C1005X7S1A225K050BC" 0402_065L 1893.01,375.07 r180 bottom value=2.2uF
C106 "C0402C104K8RACTU" 0402 2203.44,608.87 r0 top value=0.1uF
C108 "GRT155C81A105KE01D" 0402L 2423,664.6 r270 top value=1uF
C113 "C0402C104K8RACTU" 0402 2269.89,1260.99 r270 bottom value=0.1uF
C114 "GRT155C81A105KE01D" 0402L 2592.89,923.38 r270 bottom value=1uF
C115 "GCM155R71E103KA37D" 0402L 1859.31,752.89 r90 bottom value=0.01uF
C116 "C0402C104K8RACTU" 0402 1848.96,890 r270 bottom value=0.1uF
C118 "GCM155R71E103KA37D" 0402L 1839,628.6 r0 bottom value=0.01uF
C119 "GRM188C81A106MA73D" 0603 1238.56,284.57 r90 bottom value=10uF
C120 "GRM188C81A106MA73D" 0603 1170.74,285.07 r90 bottom value=10uF
C121 "C3216X6S1A226M160AB" 1206_180L 1084.38,309.27 r270 bottom value=22uF
C122 "C3216X6S1A226M160AB" 1206_180L 1003.13,309 r270 bottom value=22uF
C123 "GCM155R71H104KE02D" 0402 2768,1406.74 r0 top value=0.1uF
C124 "C1005X7S1A225K050BC" 0402_065L 2633.47,868.02 r180 bottom value=2.2uF
C125 "C0402C104K8RACTU" 0402 2665.14,907.54 r180 bottom value=0.1uF
C126 "C0402C104K8RACTU" 0402 2085.08,492.65 r0 bottom value=0.1uF
C127 "GRT155C81A105KE01D" 0402L 2186.69,505.45 r0 bottom value=1uF
C128 "GRM188C81A106MA73D" 0603 2398.91,330.26 r90 bottom value=10uF
C129 "GRM188C81A106MA73D" 0603 2326.75,330.26 r90 bottom value=10uF
C130 "C3216X6S1A226M160AB" 1206_180L 2250.46,348.82 r270 bottom value=22uF
C131 "C3216X6S1A226M160AB" 1206_180L 2161.46,347.44 r270 bottom value=22uF
C132 "885012005063" 0402 2851.75,1362.4 r90 top value=220pF
C133 "GCM155R71H104KE02D" 0402 1685.69,200.71 r90 bottom value=0.1uF
C134 "GCM155R71H104KE02D" 0402 2164.38,276.25 r270 top value=0.1uF
C135 "GRM188Z71A106MA73D" 0603 2077.15,251.31 r270 top value=10uF
C136 "GRT155C81A105KE01D" 0402L 2244,239.6 r180 top value=1uF
C137 "GRT155C81A105KE01D" 0402L 2307,387.6 r0 top value=1uF
C138 "C0402C104K8RACTU" 0402 1308,272.6 r180 top value=0.1uF
C139 "C1608X7S1A475K080AC" 0603L 2015.1,384.8 r270 top value=4.7uF
C140 "C0402C104K8RACTU" 0402 2145.41,896.26 r90 top value=0.1uF
C141 "C1608X7S1A475K080AC" 0603L 2214.74,709.19 r90 top value=4.7uF
C142 "C0402C104K8RACTU" 0402 2164.74,707.22 r270 top value=0.1uF
C143 "C0402C104K8RACTU" 0402 1604.4,520.77 r180 top value=0.1uF
C144 "C0402C104K8RACTU" 0402 1604.25,472.34 r180 top value=0.1uF
C145 "C1608X7S1A475K080AC" 0603L 2222.39,838.85 r0 top value=4.7uF
C146 "C0402C104K8RACTU" 0402 2188.53,788.54 r180 top value=0.1uF
C147 "GCM1555C1H8R0DA16D" 0402L 2195.43,547.51 r0 top
C148 "GCM1555C1H8R0DA16D" 0402L 2104.92,547.51 r180 top
C149 "GCM188R71C105KA64D" 0603 1738.57,400.73 r180 top value=1uF
C150 "C0402C104K8RACTU" 0402 1747.8,456.06 r0 top value=0.1uF
C151 "GCM188R71C105KA64D" 0603 1529.11,723.04 r0 top value=1uF
C152 "C0402C104K8RACTU" 0402 1731.16,1084.69 r90 top value=0.1uF
C153 "C0402C104K8RACTU" 0402 1889.06,1072.47 r180 top value=0.1uF
C157 "CL21B106KOQNNNE" 0805L 2889.83,750.46 r180 bottom value=10uF
C158 "C0402C104K8RACTU" 0402 2984.65,658.22 r0 top value=0.1uF
D1 "PMEG3020EP,115" SOD-128 2736.44,1009.5 r0 top value=30V
D2 "PMEG3020EP,115" SOD-128 2422.41,83.16 r0 top value=30V
D3 "TLMY1000-GS08" TLMx1000_Yellow 1361.24,858.87 r90 top value=Yellow
D4 "SZP6SMB6.8AT3G" SMB 2522,671.6 r90 top value=5.8V
D5 "APHHS1005CGCK" APHHS1005_Green 592.69,221.68 r90 top value=Green
D6 "APHHS1005CGCK" APHHS1005_Green 439.08,71.69 r0 top value=Green
D7 "APHHS1005CGCK" APHHS1005_Green 1136.94,122.48 r0 top value=Green
D8 "PMEG3020EP,115" SOD-128 2635,1317.6 r90 top value=30V
D9 "APHHS1005SURCK" APHHS1005_Red 908.35,1420.33 r180 top value=Red
D10 "TLMY1000-GS08" TLMx1000_Yellow 1456.4,800.77 r0 top value=Yellow
D12 "PMEG3020EP,115" SOD-128 2668.99,896.02 r0 top value=30V
F1 "32V, 5A" 1206 2507.4,429.46 r270 top
FB1 "BLM21PG300SH1D" 0805_HV 2460.75,179.55 r0 top value="30 ohm"
FB2 "BLM21PG300SH1D" 0805_HV 2460.75,269.12 r0 top value="30 ohm"
FID1 "Fiducial" Fiducial10-20 2874.02,1476.38 r90 top locked
FID2 "Fiducial" Fiducial10-20 275.58,1476.39 r90 top locked
FID3 "Fiducial" Fiducial10-20 2874.02,1476.38 r180 bottom locked
FID4 "Fiducial" Fiducial10-20 275.58,1476.39 r90 bottom locked
FID5 "Fiducial" Fiducial10-20 275.59,78.74 r180 bottom locked
FID6 "Fiducial" Fiducial10-20 275.59,78.74 r90 top locked
J1 "61300311021" Wurth_61300311021 2163.91,1397.45 r180 top locked
J2 "0022288072" FP-0022288072_HDR7-MFG 1608.83,1544.36 r0 top locked
J3 "M50-3930342" FP-M50-3930342_HDR3-MFG 2447.23,1522.93 r180 top
J4 "M50-3930442" FP-M50-3930442_HDR4-Recommended_Land_Pattern 2707.04,1525.96 r180 top
J5 "105017-0001" CONN_105017-0001 3039.37,1171.38 r90 top
J6 "QSH-030-01-L-D-A" Samtec_QSH-030-01-X-D-A 1022.21,916.8 r180 bottom locked
J7 "PJ-002AH" CUI_PJ-002AH 2728.35,235.81 r0 top
J8 "BC050-12A-K0-0200-0160-0480-LB" FP-BC050-12A-K0-0200-0160-0480-LB_HDR12-MFG -178.72,858.45 r90 bottom
J9 "BC084-12-A-0390-L-C" FP-BC084-12-A-0390-L-C_CONN_RCPT12-MFG 1088.05,1403.29 r0 top locked
J10 "105017-0001" CONN_105017-0001 3039.37,629.99 r270 bottom locked
L1 "LQM2MPZR10MJHL" "FP-LQM2MPZR10MJHL_0806 (2016)-MFG" 1170.43,169.85 r270 bottom value=0.1uH
L2 "BLM15HG601SN1D" 0402L 2254.74,701.32 r270 top value="600 ohm"
L3 "BLM15HG601SN1D" 0402L 2195.5,903.19 r270 top value="600 ohm"
L5 "LQM2MPZR10MJHL" "FP-LQM2MPZR10MJHL_0806 (2016)-MFG" 1036.11,168.47 r270 bottom value=0.1uH
L6 "LQM2MPZR10MJHL" "FP-LQM2MPZR10MJHL_0806 (2016)-MFG" 2148.78,207.73 r0 bottom value=0.1uH
L7 "BLM15HG601SN1D" 0402L 1654.28,408.56 r270 top value="600 ohm"
L8 "BLM15PD300SZ1D" 0402L 2868.49,841.86 r90 top
L9 "BLM15PD300SZ1D" 0402L 2871.65,1053.41 r270 top
L14 "DFE201210U-R47M=P2" "FP-DFE201210U-R47M=P2_0805 (2012)-MFG" 1305.48,275.45 r270 bottom value=0.47uH
L15 "DFE201210U-R47M=P2" "FP-DFE201210U-R47M=P2_0805 (2012)-MFG" 2471.34,317.76 r270 bottom value=0.47uH
Logo1 "Texas Instruments" TI_Stacked_Overlay_Small -37.24,818.74 r0 top
Logo2 "CE Mark" CE_Mark_5mm 1516.26,665.79 r180 bottom
LOGO3 "FCC disclaimer" FCC_disclaimer 1664.62,4635.57 r180 bottom (schematic designator Logo3)
Logo4 "WEEE logo" WEEE_Minimum 180.88,1268.11 r90 top
Q1 "SSM3K35AMFV,L3F" FP-SSM3K35AMFV,L3F_SOT-723-MFG 541.43,235.6 r90 top
Q2 "BSS123W-7-F" SOT-323 1290.91,852.23 r90 top value=100V
Q3 "SSM3K35AMFV,L3F" FP-SSM3K35AMFV,L3F_SOT-723-MFG 1265,341.6 r90 top
Q4 "SSM3K35AMFV,L3F" FP-SSM3K35AMFV,L3F_SOT-723-MFG 1135.92,78 r0 top
R1 "MCT06030Z0000ZP500" 0603 2766,1143.6 r270 top value=0
R2 "CRCW040210K0FKED" 0402L 2568.71,39.05 r0 bottom value=10.0k
R3 "ERJ-2GE0R00X" FP-ERJ-2GE0R00X_0402-MFG 2305.78,1472.96 r0 bottom value=0
R4 "RC0402FR-0710KL" FP-RC0402FR-0710KL_0402-IPC_B -324.72,837.53 r180 bottom value=10k
R5 "CRCW040210K0FKED" 0402L 205.72,910.41 r90 top value=10.0k
R6 "CRCW04024K70JNED" 0402 293,1034.6 r270 top value=4.7k
R7 "CRCW040210K0FKED" 0402L 1410.82,1051.2 r270 bottom value=10.0k
R8 "CRCW040210K0FKED" 0402L 1692.31,831.48 r270 bottom value=10.0k
R9 "RC0402FR-0710KL" FP-RC0402FR-0710KL_0402-IPC_B 2161.73,46.65 r180 bottom value=10k
R10 "CRCW040210K0FKED" 0402L 600.71,1520.36 r0 bottom value=10.0k
R11 "CRCW0402100KFKED" 0402 1971.93,297.59 r270 bottom value=100k
R12 "CRCW040210K0FKED" 0402L 354.19,1387.88 r90 bottom value=10.0k
R13 "CRCW0402750RFKED" 0402L 1583.42,104.1 r180 top value=750
R14 "CRCW040210K0FKED" 0402L 2658,39.82 r180 bottom value=10.0k
R15 "ERJ-2GE0R00X" FP-ERJ-2GE0R00X_0402-MFG 751.09,1246.42 r180 top value=0
R16 "CRCW0402750RFKED" 0402L 804.01,1201.3 r180 top value=750
R17 "CRCW040210K0FKED" 0402L 2857.02,1248.69 r0 top value=10.0k
R18 "ERJ-2GE0R00X" FP-ERJ-2GE0R00X_0402-MFG 2622.02,1260.98 r0 bottom value=0
R19 "ERJ-2GE0R00X" FP-ERJ-2GE0R00X_0402-MFG 2740.1,1225.35 r0 bottom value=0
R20 "RC0402FR-0710KL" FP-RC0402FR-0710KL_0402-IPC_B -228.79,861.86 r180 top value=10k
R21 "CRCW04021K00FKED" 0402 2727.38,1266.23 r180 bottom value=1.00k
R22 "CRCW040210K0FKED" 0402L 2558.1,1290.91 r90 top value=10.0k
R23 "CRCW040210K0FKED" 0402L 122.49,1156.44 r270 bottom value=10.0k
R24 "ERJ-2GE0R00X" FP-ERJ-2GE0R00X_0402-MFG 1807.46,1166.95 r0 bottom value=0
R25 "ERJ-2GE0R00X" FP-ERJ-2GE0R00X_0402-MFG 2457,55.6 r180 bottom value=0
R26 "ERJ-2GE0R00X" FP-ERJ-2GE0R00X_0402-MFG 1814.16,1102.37 r90 bottom value=0
R27 "CRCW040210K0FKED" 0402L 272.7,1186.6 r0 bottom value=10.0k
R28 "ERJ-2GEJ511X" 0402L 1138.72,151 r0 top value=510
R29 "ERJ-2GE0R00X" FP-ERJ-2GE0R00X_0402-MFG 2421.9,222.2 r180 bottom value=0
R30 "MCT06030Z0000ZP500" 0603 1330.65,1282.48 r270 bottom value=0
R31 "MCT06030Z0000ZP500" 0603 2789.07,1369.2 r270 bottom value=0
R32 "MCT06030Z0000ZP500" 0603 2727.6,1369.96 r270 bottom value=0
R33 "CRCW04024K70JNED" 0402 203.73,1156.14 r180 top value=4.7k
R34 "ERJ-2GE0R00X" FP-ERJ-2GE0R00X_0402-MFG 811.41,1238.54 r90 bottom value=0
R35 "RC0402JR-070RP" FP-RC0402JR-070RP_0402-MFG 2537.99,532.44 r0 bottom value=0
R36 "CRCW040240K2FKEDC" FP-CRCW040240K2FKEDC_0402-MFG 2640,551.6 r180 bottom value=40.2k
R37 "ERJ-2GE0R00X" FP-ERJ-2GE0R00X_0402-MFG 1242.01,1191.07 r180 bottom value=0
R38 "ERJ-2GE0R00X" FP-ERJ-2GE0R00X_0402-MFG 782.6,1238.77 r90 bottom value=0
R39 "ERJ-2GE0R00X" FP-ERJ-2GE0R00X_0402-MFG 1242.01,1151.87 r180 bottom value=0
R40 "ERJ-2GE0R00X" FP-ERJ-2GE0R00X_0402-MFG 794.15,1156.72 r180 bottom value=0
R41 "ERJ-2GE0R00X" FP-ERJ-2GE0R00X_0402-MFG 1242.01,1112.68 r180 bottom value=0
R42 "ERJ-2GE0R00X" FP-ERJ-2GE0R00X_0402-MFG 794.28,1123.93 r180 bottom value=0
R43 "ERJ-2GE0R00X" FP-ERJ-2GE0R00X_0402-MFG 1653.28,104.1 r180 top value=0
R44 "RC0402FR-0710KL" FP-RC0402FR-0710KL_0402-IPC_B -261.69,608.86 r0 bottom value=10k
R45 "RT0402FRE0733R2L" FP-RT0402FRE0733R2L_0402-MFG -223.34,591.06 r180 top value=33.2
R46 "RT0402FRE0733R2L" FP-RT0402FRE0733R2L_0402-MFG -242.5,676.58 r0 bottom value=33.2
R47 "RT0402FRE0733R2L" FP-RT0402FRE0733R2L_0402-MFG -259.28,642.85 r0 bottom value=33.2
R48 "RT0402FRE0733R2L" FP-RT0402FRE0733R2L_0402-MFG -225.79,647.29 r180 top value=33.2
R49 "RC0402FR-0710KL" FP-RC0402FR-0710KL_0402-IPC_B -348.59,625.44 r0 bottom value=10k
R50 "RC0402FR-1047K5L" FP-RC0402FR-1047K5L_0402-MFG -212.01,717.93 r0 bottom value=47.5k
R51 "RT0402FRE0733R2L" FP-RT0402FRE0733R2L_0402-MFG -349.43,584.82 r180 bottom value=33.2
R52 "ERJ-2GE0R00X" FP-ERJ-2GE0R00X_0402-MFG 1242.01,1073.49 r180 bottom value=0
R53 "ERJ-2GE0R00X" FP-ERJ-2GE0R00X_0402-MFG 794.35,1091.37 r180 bottom value=0
R54 "CRCW040210K0FKED" 0402L 479.26,362.69 r180 bottom value=10.0k
R55 "ERJ-2GE0R00X" FP-ERJ-2GE0R00X_0402-MFG 648.64,293.12 r180 bottom value=0
R56 "ERJ-2GE0R00X" FP-ERJ-2GE0R00X_0402-MFG 483.05,323.15 r0 bottom value=0
R57 "ERJ-2GE0R00X" FP-ERJ-2GE0R00X_0402-MFG 597,408.84 r90 bottom value=0
R58 "ERJ-2GE0R00X" FP-ERJ-2GE0R00X_0402-MFG 1242.01,1034.29 r180 bottom value=0
R59 "ERJ-2GE0R00X" FP-ERJ-2GE0R00X_0402-MFG 1242.01,738.31 r180 bottom value=0
R60 "ERJ-2GE0R00X" FP-ERJ-2GE0R00X_0402-MFG 1242.01,699.12 r180 bottom value=0
R61 "ERJ-2GE0R00X" FP-ERJ-2GE0R00X_0402-MFG 1242.01,659.92 r180 bottom value=0
R62 "ERJ-2GE0R00X" FP-ERJ-2GE0R00X_0402-MFG 1242.01,620.73 r180 bottom value=0
R63 "ERJ-2GE0R00X" FP-ERJ-2GE0R00X_0402-MFG 1242.01,581.08 r180 bottom value=0
R64 "CRCW0402220RJNED" 0402 925.84,1486.09 r90 top value=220
R65 "CRCW040210K0FKED" 0402L 884.63,1491.13 r270 top value=10.0k
R66 "ERJ-2GEJ511X" 0402L 1057,122.6 r180 top value=510
R67 "ERJ-2GE0R00X" FP-ERJ-2GE0R00X_0402-MFG 873.23,1200.7 r180 top value=0
R68 "CRCW040261R9FKED" 0402L 2368.79,1401.45 r180 top value=61.9
R69 "ERJ-2GE0R00X" FP-ERJ-2GE0R00X_0402-MFG 2521.49,1226.67 r0 top value=0
R70 "CRCW04021K00FKED" 0402 1183.3,786.36 r0 top value=1.00k
R71 "CRCW040210K0FKED" 0402L 2306.28,1510.51 r0 bottom value=10.0k
R72 "CRCW040210K0FKED" 0402L 2843,1198.6 r180 bottom value=10.0k
R73 "WR04X1003FTL" FP-WR04X1003FTL_0402-IPC_B -333.49,784.56 r180 bottom value=100k
R74 "WR04X1003FTL" FP-WR04X1003FTL_0402-IPC_B -336.61,927.39 r180 bottom value=100k
R75 "RC0402FR-0710KL" FP-RC0402FR-0710KL_0402-IPC_B -324.51,877.74 r180 bottom value=10k
R76 "CRCW040210K0FKED" 0402L 2204.61,372.62 r0 top value=10.0k
R77 "RC0402JR-070RP" FP-RC0402JR-070RP_0402-MFG -550.08,953.21 r180 bottom value=0
R78 "ERJ-2GE0R00X" FP-ERJ-2GE0R00X_0402-MFG 2249.94,1192.52 r0 top value=0
R79 "CRCW040261R9FKED" 0402L 2444.87,1401.45 r180 top value=61.9
R80 "ERJ-2GE0R00X" FP-ERJ-2GE0R00X_0402-MFG 2538.58,1150.59 r180 top value=0
R81 "CRCW040210K0FKED" 0402L 1855,1063.6 r270 bottom value=10.0k
R82 "CRCW040210K0FKED" 0402L 2201.44,1253.44 r270 bottom value=10.0k
R83 "CRCW04021K00FKED" 0402 1322.56,983.8 r90 bottom value=1.00k
R86 "RC0402FR-071KL" FP-RC0402FR-071KL_0402-IPC_B -985.39,956.6 r180 bottom value=1k
R88 "ERJ-2GE0R00X" FP-ERJ-2GE0R00X_0402-MFG 2856,1280.21 r180 top value=0
R90 "CRCW040210K0FKED" 0402L 695.76,1487.02 r180 top value=10.0k
R91 "CRCW040210K0FKED" 0402L 765.35,1396.73 r90 bottom value=10.0k
R93 "RT0402FRE0733R2L" FP-RT0402FRE0733R2L_0402-MFG -172.96,781.9 r180 top value=33.2
R94 "CRCW040210K0FKED" 0402L 2497.71,222.27 r180 bottom value=10.0k
R97 "CRCW040210K0FKED" 0402L 2199.4,1292.25 r270 top value=10.0k
R98 "CRCW040210K0FKED" 0402L 2163.94,1291.86 r270 top value=10.0k
R99 "CRCW0402100KFKED" 0402 1805.44,1131.87 r270 top value=100k
R101 "CRCW040210K0FKED" 0402L 2568.71,71.79 r180 bottom value=10.0k
R102 "CRCW040210K0FKED" 0402L 2321.22,261.96 r270 top value=10.0k
R103 "CRCW040210K0FKED" 0402L 2658,72.6 r0 bottom value=10.0k
R104 "CRCW040210K0FKED" 0402L 387.45,467.79 r0 bottom value=10.0k
R105 "CRCW040210K0FKED" 0402L 153,485.6 r180 bottom value=10.0k
R106 "CRCW040210K0FKED" 0402L 536,148.6 r180 bottom value=10.0k
R107 "CRCW040210K0FKED" 0402L 536,110.6 r180 bottom value=10.0k
R108 "ERJ-2GE0R00X" FP-ERJ-2GE0R00X_0402-MFG 116.01,644.91 r180 bottom value=0
R109 "ERJ-2GE0R00X" FP-ERJ-2GE0R00X_0402-MFG 533.56,219.86 r180 bottom value=0
R110 "ERJ-2GE0R00X" FP-ERJ-2GE0R00X_0402-MFG 128.61,596.65 r270 bottom value=0
R111 "ERJ-2GE0R00X" FP-ERJ-2GE0R00X_0402-MFG 694,240.6 r0 bottom value=0
R112 "CRCW040210K0FKED" 0402L 379.03,500 r180 bottom value=10.0k
R113 "CRCW040210K0FKED" 0402L 387.45,437.96 r180 bottom value=10.0k
R114 "CRCW040210K0FKED" 0402L 153,519.6 r0 bottom value=10.0k
R115 "CRCW040210K0FKED" 0402L 699.53,76.05 r180 bottom value=10.0k
R116 "CRCW040210K0FKED" 0402L 536,181.6 r0 bottom value=10.0k
R117 "CRCW040210K0FKED" 0402L 536,75.6 r0 bottom value=10.0k
R119 "RC0402JR-070RP" FP-RC0402JR-070RP_0402-MFG 1432.18,270.17 r270 bottom value=0
R120 "CRCW0402100KFKED" 0402 2361.22,305.27 r270 top value=100k
R121 "WR04X6802FTL" FP-WR04X6802FTL_0402-MFG 1464.61,269.17 r90 bottom value=68k
R122 "CRCW040233R2FKED" 0402 1971.24,1283.79 r90 bottom value=33.2
R123 "CRCW040210K0FKED" 0402L 1405.65,1053.75 r90 top value=10.0k
R124 "CRCW040233R2FKED" 0402 2021.22,1283.79 r90 bottom value=33.2
R125 "CRCW040233R2FKED" 0402 2071.2,1266.55 r90 bottom value=33.2
R126 "CRCW040233R2FKED" 0402 2144.09,1270.37 r90 bottom value=33.2
R127 "ERJ-2GE0R00X" FP-ERJ-2GE0R00X_0402-MFG 1760.74,925.16 r270 bottom value=0
R128 "ERJ-2GE0R00X" FP-ERJ-2GE0R00X_0402-MFG 1407.48,922.09 r90 bottom value=0
R129 "MCT06030Z0000ZP500" 0603 461,568.6 r90 top value=0
R134 "WSL1206R0200FEB" FP-WSL1206R0200FEB_1206-MFG 1591.25,75.52 r0 bottom value=20m
R135 "CRCW040210K0FKED" 0402L 1490.17,398.71 r180 bottom value=10.0k
R136 "CRCW040210K0FKED" 0402L 1490.17,353.71 r180 bottom value=10.0k
R137 "ERJ-2GE0R00X" FP-ERJ-2GE0R00X_0402-MFG 1632.32,422.36 r90 bottom value=0
R138 "CRCW040210K0FKED" 0402L 1505.89,1044.38 r90 top value=10.0k
R139 "ERJ-2GE0R00X" FP-ERJ-2GE0R00X_0402-MFG 1689,318.6 r0 bottom value=0
R141 "ERJ-2GEJ511X" 0402L 612,169 r0 top value=510
R142 "CRCW040210K0FKED" 0402L 1698,287.6 r180 bottom value=10.0k
R148 "CRCW040210K0FKED" 0402L 1490.17,433.69 r0 bottom value=10.0k
R150 "CRCW040210K0FKED" 0402L 1509.86,299.03 r90 bottom value=10.0k
R151 "ERJ-2GE0R00X" FP-ERJ-2GE0R00X_0402-MFG 566.99,292.39 r0 bottom value=0
R152 "CRCW040210K0FKED" 0402L 87.87,1156.14 r90 bottom value=10.0k
R157 "CRCW040210K0FKED" 0402L 1766.32,1238.66 r270 bottom value=10.0k
R158 "CRCW040210K0FKED" 0402L 1800.31,1238.66 r90 bottom value=10.0k
R159 "ERJ-2GE0R00X" FP-ERJ-2GE0R00X_0402-MFG 1789.48,1304.1 r0 bottom value=0
R160 "ERJ-2GE0R00X" FP-ERJ-2GE0R00X_0402-MFG 1789.48,1355.38 r0 bottom value=0
R161 "CRCW040210K0FKED" 0402L 1448.43,1243.17 r270 bottom value=10.0k
R162 "CRCW040210K0FKED" 0402L 1446,1332.6 r270 bottom value=10.0k
R165 "CRCW040210K0FKED" 0402L 909.27,146.66 r270 top value=10.0k
R167 "CRCW040210K0FKED" 0402L 1721.82,273.16 r0 top value=10.0k
R168 "CRCW040210K0FKED" 0402L 1660,230.6 r0 top value=10.0k
R169 "ERJ-2GEJ101X" 0402L 2785.7,614.32 r0 bottom value=100
R170 "ERJ-2GE0R00X" FP-ERJ-2GE0R00X_0402-MFG 2578.12,684.21 r90 bottom value=0
R171 "ERJ-2GEJ511X" 0402L 506,182.97 r180 top value=510
R172 "ERJ-2GEJ511X" 0402L 1288.87,781.11 r180 top value=510
R173 "RC0402JR-070RP" FP-RC0402JR-070RP_0402-MFG 1200.25,350.14 r90 top value=0
R174 "ERJ-2GEJ511X" 0402L 407.4,132.35 r0 top value=510
R175 "CRCW0402100KFKEDC" FP-CRCW0402100KFKEDC_0402-IPC_B 1494.12,1155.09 r180 bottom value=100k
R176 "RC0402JR-070RP" FP-RC0402JR-070RP_0402-MFG 1520.93,1120.61 r0 bottom value=0
R177 "CRCW0402100KFKEDC" FP-CRCW0402100KFKEDC_0402-IPC_B 1195.29,280.87 r0 top value=100k
R178 "CRCW040218K0FKEDC" FP-CRCW040218K0FKEDC_0402-IPC_B 1382.99,404.48 r90 bottom value=18k
R179 "ERJ-2GEJ511X" 0402L 1283.31,925.75 r180 top value=510
R180 "CRCW040218K0FKEDC" FP-CRCW040218K0FKEDC_0402-IPC_B 2559.5,468.51 r90 bottom value=18k
R181 "ERJ-2GE0R00X" FP-ERJ-2GE0R00X_0402-MFG 1874.88,1226.06 r0 bottom value=0
R184 "CRCW040210K0FKED" 0402L 1593.29,387.57 r0 top value=10.0k
R185 "CRCW04022K20JNED" 0402L 1685.72,332.39 r270 top value=2.2k
R186 "CRCW040233R2FKED" 0402 2102,1024.67 r90 top value=33.2
R187 "CRCW040233R2FKED" 0402 2049.03,1178.15 r0 top value=33.2
R188 "ERJ-2GE0R00X" FP-ERJ-2GE0R00X_0402-MFG 1874.9,1167.93 r0 bottom value=0
R189 "ERJ-2GE0R00X" FP-ERJ-2GE0R00X_0402-MFG 1909.14,1200.19 r180 top value=0
R190 "ERJ-2GE0R00X" FP-ERJ-2GE0R00X_0402-MFG 1841.07,1008.31 r0 bottom value=0
R191 "CRCW04021K00FKED" 0402 2536.85,1310.42 r90 bottom value=1.00k
R192 "WSL1206R0400FEB" FP-WSL1206R0400FEB_1206-MFG 2256.59,156.6 r270 bottom value=40m
R193 "WSL1206R0400FEB" FP-WSL1206R0400FEB_1206-MFG 908.71,148.98 r90 bottom value=40m
R194 "CRCW04021K00FKED" 0402 2485.43,1310.42 r90 bottom value=1.00k
R195 "CRCW04021K00FKED" 0402 2436.08,1310.76 r90 bottom value=1.00k
R196 "CRCW04021K00FKED" 0402 2385.51,1310.76 r90 bottom value=1.00k
R197 "ERJ-2GE0R00X" FP-ERJ-2GE0R00X_0402-MFG 1369,587.6 r0 top value=0
R198 "RC0402JR-070RP" FP-RC0402JR-070RP_0402-MFG 1310.49,803.03 r0 bottom value=0
R199 "ERJ-2GE0R00X" FP-ERJ-2GE0R00X_0402-MFG 1455.55,587.64 r0 top value=0
R200 "WSL1206R0400FEB" FP-WSL1206R0400FEB_1206-MFG 257.42,328.48 r180 bottom value=40m
R201 "CRCW0402100KFKEDC" FP-CRCW0402100KFKEDC_0402-IPC_B 1315.12,855.6 r180 bottom value=100k
R202 "CRCW040249R9FKED" 0402L 2644.1,1061.77 r90 bottom value=49.9
R203 "CRCW040210K0FKED" 0402L 1583.42,139.1 r180 top value=10.0k
R204 "CRCW04027K87FKED" 0402L 1218.15,212.89 r180 top value=7.87k
R205 "CRCW040282K5FKED" 0402L 1583.42,176.6 r180 top value=82.5k
R206 "CRCW040210K0FKED" 0402L 763.62,1115.15 r0 top value=10.0k
R207 "CRCW04027K87FKED" 0402L 804.27,1165.62 r0 top value=7.87k
R208 "CRCW040282K5FKED" 0402L 819.66,1109.71 r90 top value=82.5k
R209 "CRCW040233R2FKED" 0402 1889.06,1155.5 r180 top value=33.2
R213 "CRCW0402220RJNED" 0402 1420.9,706.87 r270 top value=220
R214 "ERJ-2GE0R00X" FP-ERJ-2GE0R00X_0402-MFG 1184,608.36 r270 top value=0
R215 "CRCW0402100KFKED" 0402 1250.68,600.84 r0 top value=100k
R216 "ERJ-2GE0R00X" FP-ERJ-2GE0R00X_0402-MFG 1673.34,1027.4 r180 top value=0
R217 "ERJ-2GE0R00X" FP-ERJ-2GE0R00X_0402-MFG 1655.35,968.12 r180 top value=0
R218 "CRCW040210K0FKED" 0402L 2279.59,794.95 r180 top value=10.0k
R219 "ERJ-2GE0R00X" FP-ERJ-2GE0R00X_0402-MFG 809.24,971.01 r180 bottom value=0
R220 "ERJ-2GE0R00X" FP-ERJ-2GE0R00X_0402-MFG 809.24,941.33 r180 bottom value=0
R221 "ERJ-2GE0R00X" FP-ERJ-2GE0R00X_0402-MFG 749.24,911.96 r180 bottom value=0
R222 "ERJ-2GE0R00X" FP-ERJ-2GE0R00X_0402-MFG 749.24,882.27 r180 bottom value=0
R223 "ERJ-2GE0R00X" FP-ERJ-2GE0R00X_0402-MFG 809.24,852.9 r180 bottom value=0
R224 "ERJ-2GE0R00X" FP-ERJ-2GE0R00X_0402-MFG 809.24,823.22 r180 bottom value=0
R225 "ERJ-2GE0R00X" FP-ERJ-2GE0R00X_0402-MFG 739.24,793.85 r180 bottom value=0
R226 "ERJ-2GE0R00X" FP-ERJ-2GE0R00X_0402-MFG 739.24,764.16 r180 bottom value=0
R227 "ERJ-2GE0R00X" FP-ERJ-2GE0R00X_0402-MFG 809.24,734.79 r180 bottom value=0
R228 "ERJ-2GE0R00X" FP-ERJ-2GE0R00X_0402-MFG 809.24,705.11 r180 bottom value=0
R229 "ERJ-2GE0R00X" FP-ERJ-2GE0R00X_0402-MFG 749.24,675.74 r180 bottom value=0
R230 "ERJ-2GE0R00X" FP-ERJ-2GE0R00X_0402-MFG 749.24,646.05 r180 bottom value=0
R231 "CRCW040210K0FKED" 0402L 2599.45,1022.42 r90 bottom value=10.0k
R233 "CRCW04021K00FKED" 0402 1990,482.6 r270 bottom value=1.00k
R234 "CRCW04024K87FKED" 0402L 2342.87,1330.76 r270 bottom value=4.87k
R236 "CRCW0402330KFKED" 0402L 1839,687.6 r180 bottom value=330k
R237 "CRCW04021K00FKED" 0402 2047,1024.73 r270 top value=1.00k
R238 "CRCW0402100KFKEDC" FP-CRCW0402100KFKEDC_0402-IPC_B 1310.78,456.59 r0 bottom value=100k
R239 "CRCW0402330KFKED" 0402L 1839,590.6 r0 bottom value=330k
R241 "ERJ-2GE0R00X" FP-ERJ-2GE0R00X_0402-MFG 2012.34,293.63 r270 bottom value=0
R242 "ERJ-2GE0R00X" FP-ERJ-2GE0R00X_0402-MFG 1920.74,442.33 r270 top value=0
R243 "ERJ-2GE0R00X" FP-ERJ-2GE0R00X_0402-MFG 1560.43,663.99 r180 top value=0
R244 "CRCW0402100KFKEDC" FP-CRCW0402100KFKEDC_0402-IPC_B 2491.48,496.28 r0 bottom value=100k
R248 "CRCW040233R2FKED" 0402 1826.69,414.59 r270 top value=33.2
R249 "CRCW040233R2FKED" 0402 1880.88,439.96 r270 top value=33.2
R251 "CRCW040233R2FKED" 0402 1545.17,841.15 r180 top value=33.2
R252 "ERJ-2GEJ511X" 0402L 1446.89,841.15 r180 top value=510
R259 "ERJ-2GE0R00X" FP-ERJ-2GE0R00X_0402-MFG 2900.13,685.94 r180 top value=0
R260 "CRCW040230K0FKED" 0402L 2907.98,584.07 r0 top value=30.0k
R261 "ERJ-2GE0R00X" FP-ERJ-2GE0R00X_0402-MFG 2934.12,526.52 r270 bottom value=0
S1 "218-6LPST" SW_218-6LPST 1023.96,1007.62 r0 top
S2 "PTS645SM43SMTR92 LFS" SW_PTS645SM43SMT 934,318.6 r0 top
S3 "KMR243GLFG" SW_KMR243GLFG 1291.37,699 r180 top
S4 "218-4LPST" SW_218-4LPST 949.68,686.36 r0 top
S5 "218-2LPST" SW_218-2LP 1369,494.6 r0 top
SW1 "AYZ0102AGRLC" FP-AYZ0102AGRLC_SMT_SW_7MM2_5MM3-MFG 1396.77,90.3 r0 top
SW2 "JS102011JCQN" FP-JS102011JCQN_SMD3-MFG 1578.11,1277.23 r180 top locked
SW3 "CJS-1200A1" FP-CJS-1200A1_SMT3-MFG 1309.92,1109.26 r270 top
TP1 "TESTPOINT" TP_25MIL-SMT 756.73,1282.4 r180 top
TP2 "TESTPOINT" TP_25MIL-SMT 342.51,1439.28 r180 top
TP3 "TESTPOINT" TP_25MIL-SMT 752.1,1371.83 r90 top
TP4 "TESTPOINT" TP_25MIL-SMT 677.26,1387.25 r180 top
TP5 "TESTPOINT" TP_25MIL-SMT -826.71,617.3 r90 bottom
TP6 "TESTPOINT" TP_25MIL-SMT -931.35,962.11 r90 bottom
TP7 "TESTPOINT" TP_25MIL-SMT -744.31,801.31 r90 bottom
TP8 "TESTPOINT" TP_25MIL-SMT 2145.55,375.86 r180 top
TP9 "TESTPOINT" TP_25MIL-SMT 646.86,412.49 r180 bottom
TP10 "TP_SM_1MM" TP_SM_1MM -624.09,693.24 r90 bottom
TP11 "TESTPOINT" TP_VIA_060RND040 2866.07,469.33 r180 top
TP12 "TESTPOINT" TP_25MIL-SMT 2317.97,183.59 r270 top
TP13 "TESTPOINT" TP_25MIL-SMT -119.98,808.16 r90 top
TP14 "TESTPOINT" TP_25MIL-SMT -840.02,963.63 r270 bottom
TP15 "TESTPOINT" TP_25MIL-SMT -617.14,964.95 r90 bottom
TP16 "TESTPOINT" TP_25MIL-SMT -1063.83,953.21 r90 bottom
U1 "XI6432BRQAAMY" AMY0101A-MFG -688.96,777.52 r180 top locked
U2 "MX25R1635FZUIH0" USON-8L -128.06,643.83 r270 bottom
U3 "TMP112AQDRLRQ1" DRL0006A 568.08,343.01 r0 bottom
U4 "TS3A5018RSVR" RSV0016A 269.85,764.16 r0 top
U5 "TCAN1042HGVDQ1" D0008A_L 2390.27,1238.23 r90 top
U6 "INA228AIDGST" DGS0010A-MFG 2424.16,139.04 r180 bottom
U7 "INA228AIDGST" DGS0010A-MFG 261.31,495.19 r270 bottom
U8 "INA228AIDGST" DGS0010A-MFG 714.66,159.91 r0 bottom
U9 "TPD4E004DRYR" DRY0006A 2864.53,1168.25 r0 top
U10 "SN65LVDS31MDREP" D0016A_N 469.11,845.53 r0 bottom
U11 "CAT24C08WI-GT3" SOIC-8 1603.85,1279.47 r0 bottom
U12 "TS3A44159PWR" PW0016A_N 1575.81,979.08 r180 bottom
U13 "TLV75533PDRVR" DRV0006A 1898.8,304.92 r270 bottom
U14 "SN65LVDS31MDREP" D0016A_N 469.11,845.53 r180 top
U15 "TS3A27518EPWR" PW0024A-MFG 506.68,1324.13 r0 top
U16 "TPS2116DRLR" DRL0008A-MFG 2256,302.6 r90 top
U17 "SN74LVC1G11DSFR" DSF0006A 1455.43,1057.69 r90 top
U18 "TLV75533PDRVR" DRV0006A 383.33,210.5 r270 bottom
U19 "TPS6285020ADRLR" DRL0008A-MFG 1320.2,389.21 r270 bottom
U20 "TPS6285020MDRLR" DRL0008A-MFG 2498.59,433.89 r270 bottom
U21 "TM4C1294NCPDTT3" PDT0128A 2224.4,874.45 r0 bottom locked
U22 "LM4040C25QDBZR" DBZ0003A_N 1898,507.6 r90 bottom
U23 "TLIN1039DDFRQ1" DDF0008A-MFG 2757.49,1300.42 r90 top
U24 "TS3A5018RSVR" RSV0016A 200.4,1096.42 r180 bottom
U25 "INA228AIDGST" DGS0010A-MFG 1592.95,265.57 r270 bottom
U26 "93LC46B-I/ST" TSSOP-8 1511.78,307.39 r180 top
U27 "FT4232HL" LQFP64_N 1859.11,752.57 r180 top locked
U28 "TS3A27518EPWR" PW0024A-MFG 542.64,1346.19 r90 bottom
U29 "TPD4E004DRYR" DRY0006A 2908.92,633.09 r0 top
Y1 "XRCGB40M000F1S2GR0" FP-XRCGB40M000F1S2GR0_SMT_CRYSTAL_2MM0_1MM6-MFG -1000.55,656.93 r90 bottom
Y2 "ECS-160-8-33Q-RES-TR" FP-ECS-160-8-33Q-RES-TR_SMT4_3MM2_2MM5-MFG 2700.7,751.49 r270 bottom
Y3 "NX3225SA-12.000M-STD-CRS-2" NDK_NX3225SA 2132.69,470.11 r90 top
ZZ1 "This Assembly Note is for PCB labels only" AssemblyNoteLabel -760.51,4214.38 r0 top
ZZ2 "These assemblies are ESD sensitive, ESD precautions shall be observed." AssemblyNote -758.1,4136.4 r0 top
ZZ3 "These assemblies must be clean and free from flux and all contaminants. Use of no clean flux is not acceptable." AssemblyNote -758.1,4049.59 r0 top
ZZ4 "These assemblies must comply with workmanship standards IPC-A-610 Class 2, unless otherwise specified." AssemblyNote -737.53,3980.86 r0 top
ZZ5 "INDICATION FOR COMPONENTS D* ARE GIVEN AT THEIR CATHODE SIDE." AssemblyNote -736.14,3893.27 r0 top

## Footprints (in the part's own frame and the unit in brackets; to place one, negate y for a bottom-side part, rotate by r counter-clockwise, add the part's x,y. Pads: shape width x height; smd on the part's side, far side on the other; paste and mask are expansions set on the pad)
0402 [mm] "0402 from SM-752 data"
  rect 0.8x0.6 smd: 1(-0.6,0) 2(0.6,0)
  silkscreen extent -1.22,-0.52 1.22,0.52, body extent -0.55,-0.3 0.55,0.3, height 0.6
